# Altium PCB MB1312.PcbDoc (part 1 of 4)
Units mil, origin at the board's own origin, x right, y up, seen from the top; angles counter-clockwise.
Board outline 2755.91 x 5249.6 mil, 6 copper layers (Top Layer, GND, Signal, PWR, GND (Mid2), Bottom Layer), stack 74.545 mil thick; 297 components, 280 nets, 1142 pads, 623 vias.
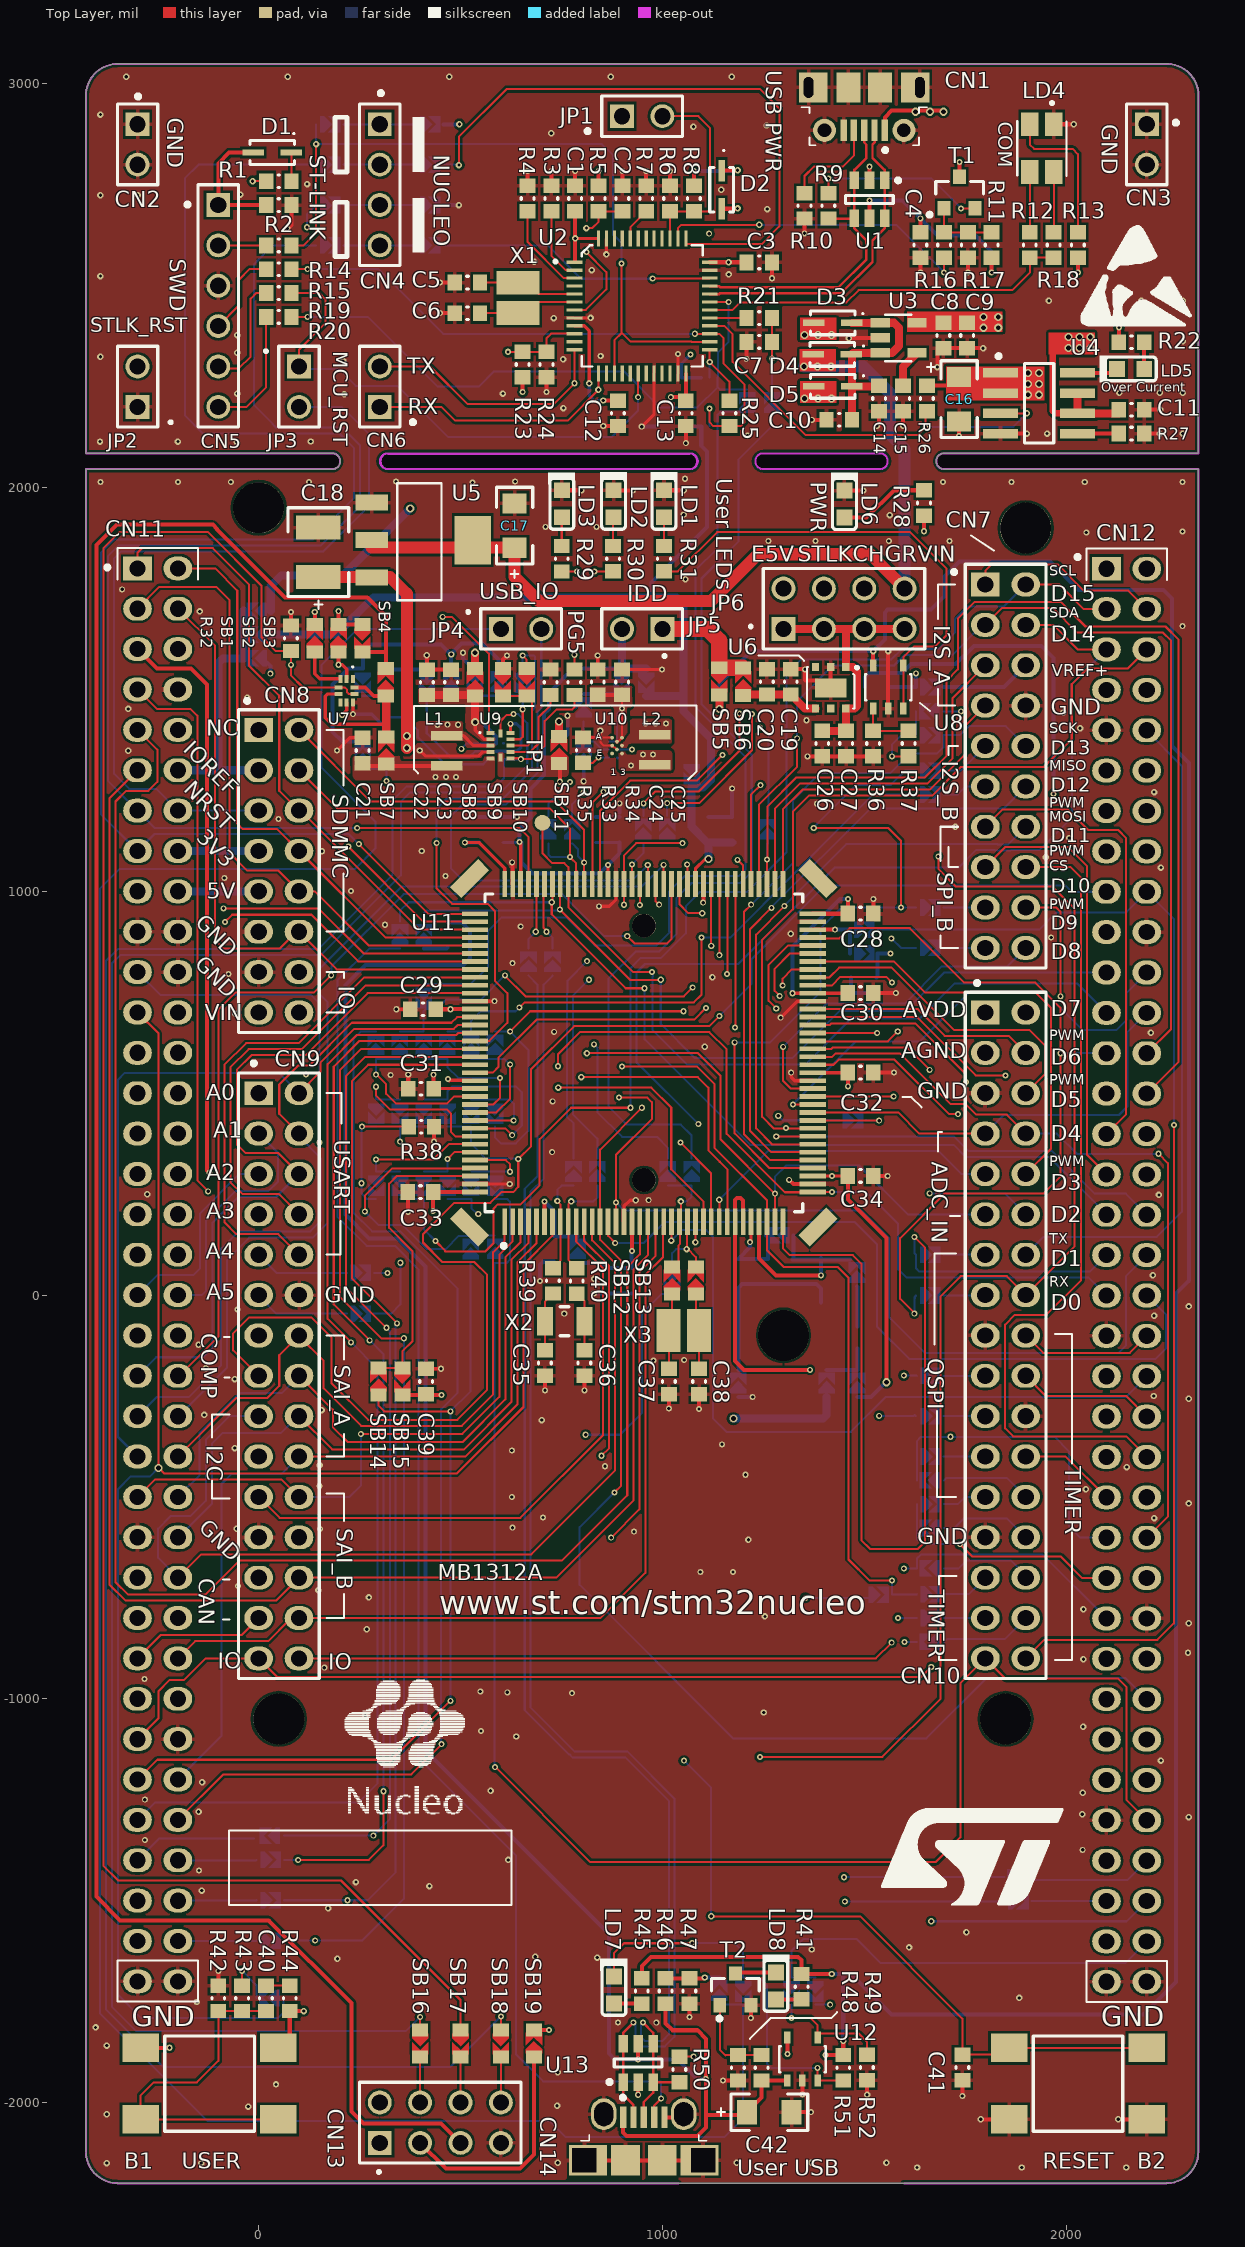
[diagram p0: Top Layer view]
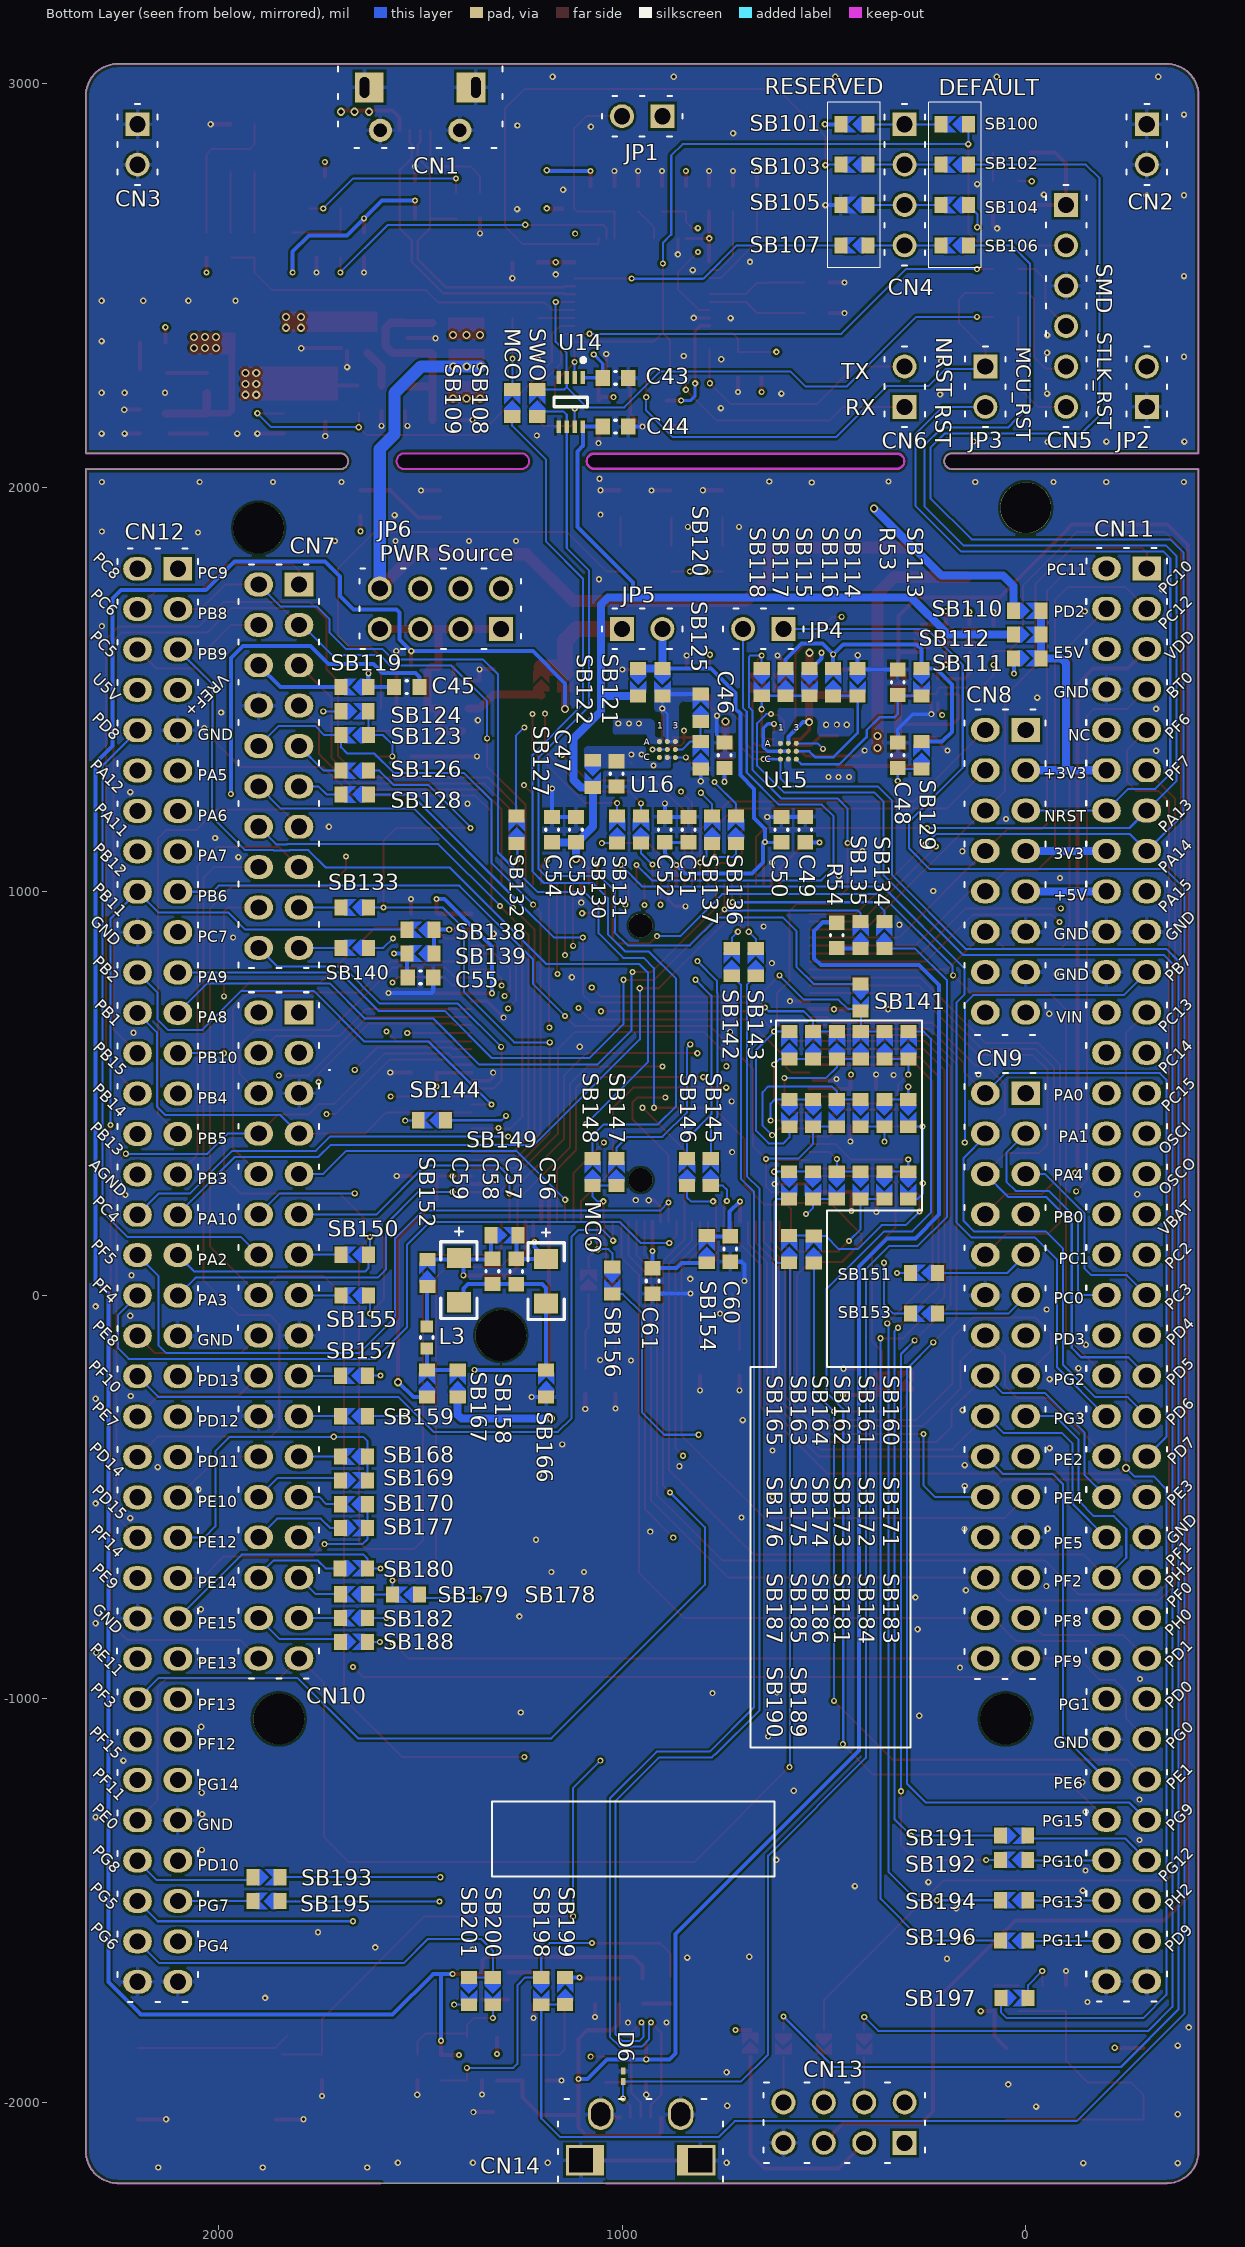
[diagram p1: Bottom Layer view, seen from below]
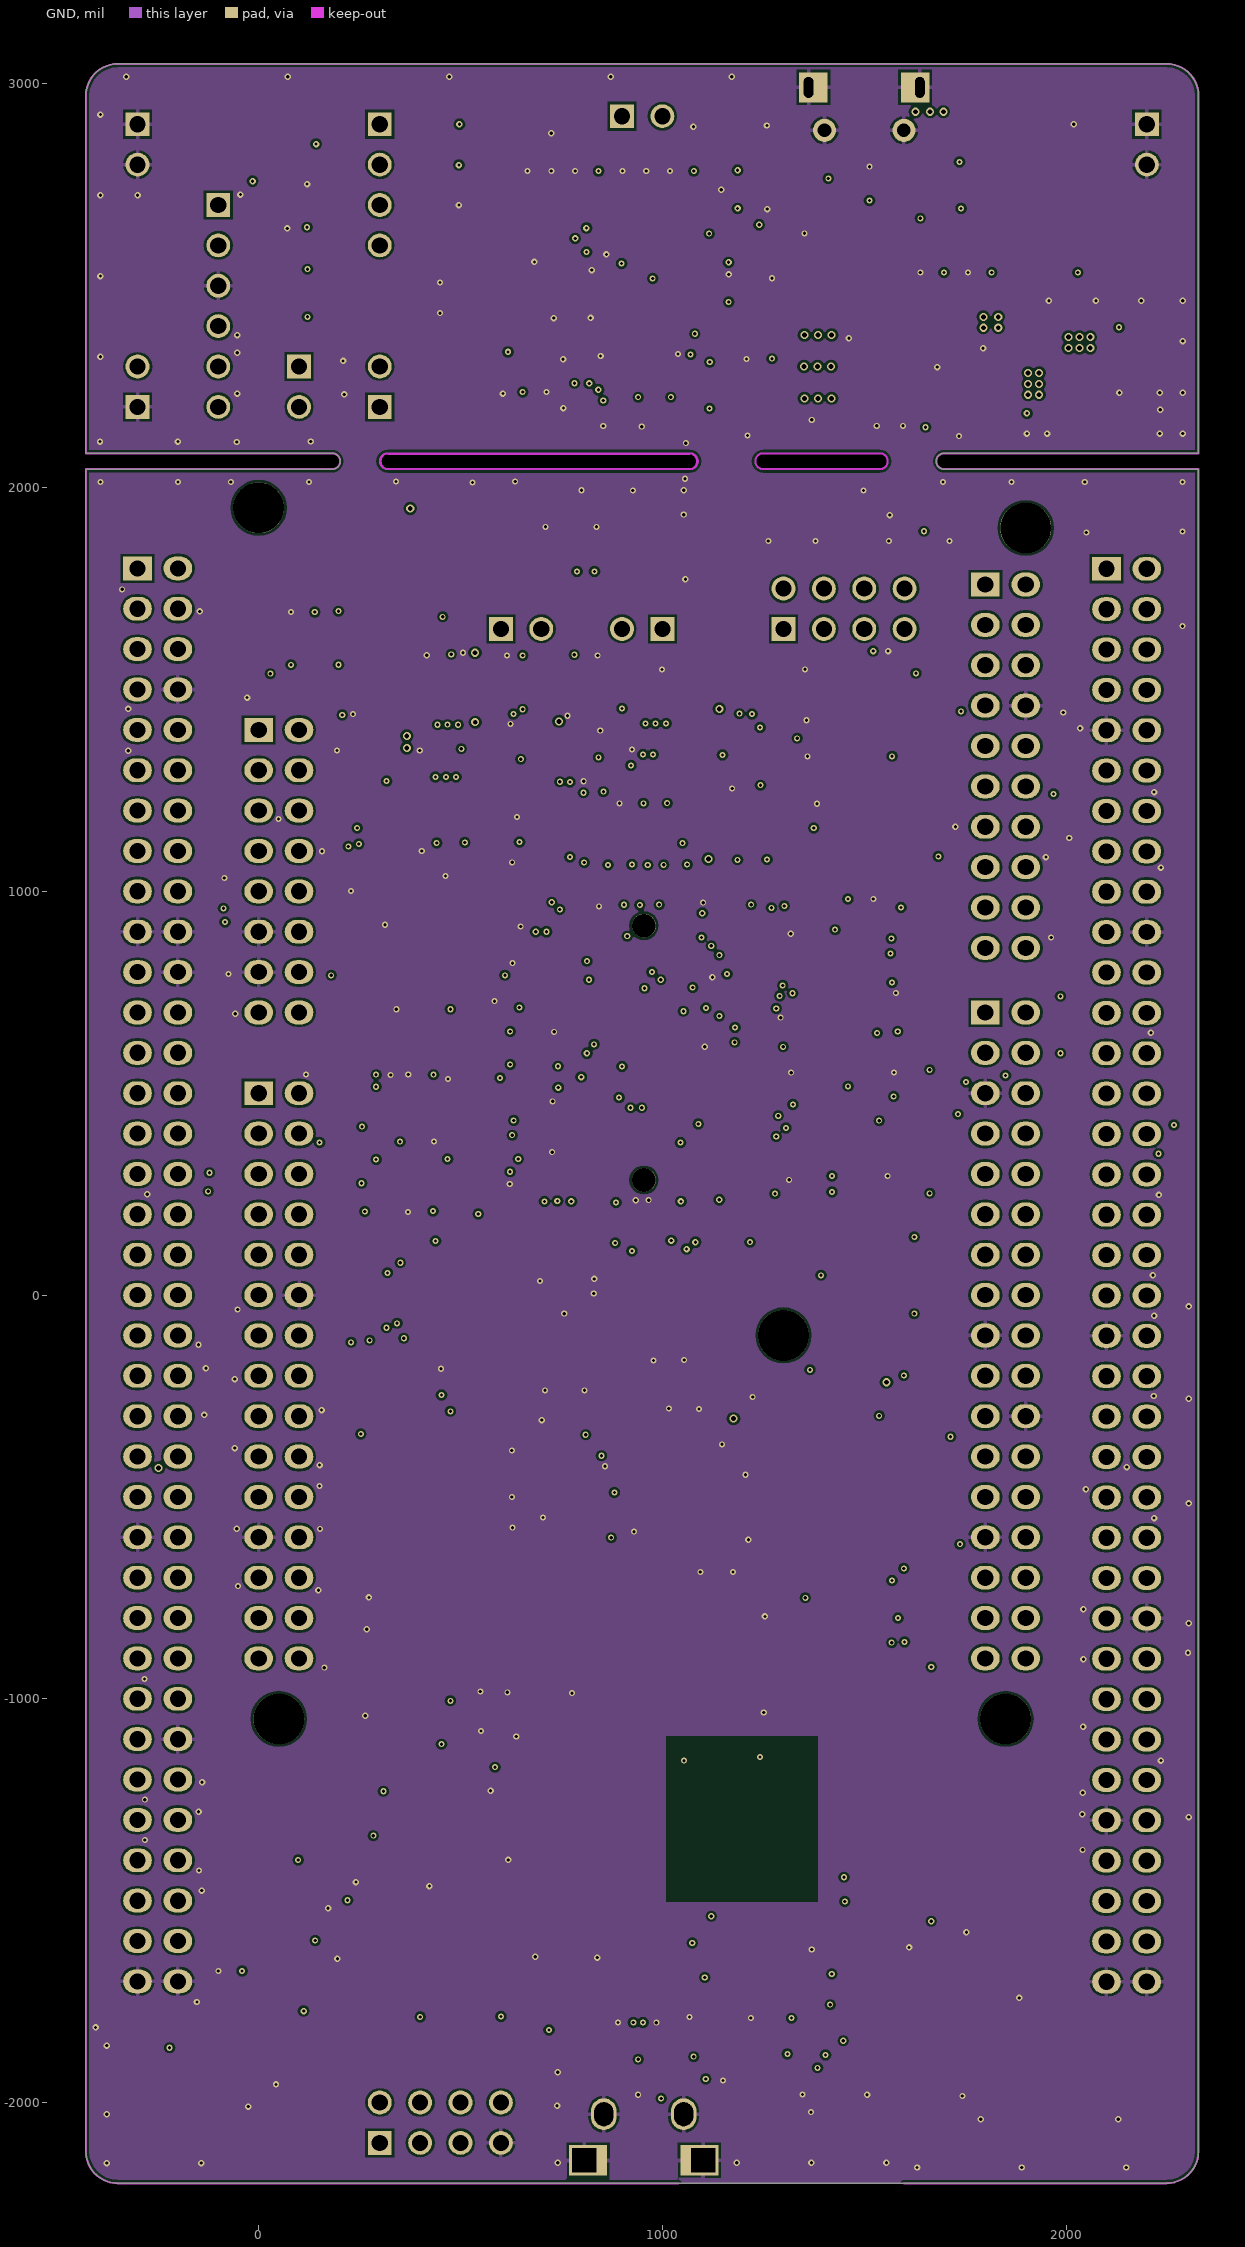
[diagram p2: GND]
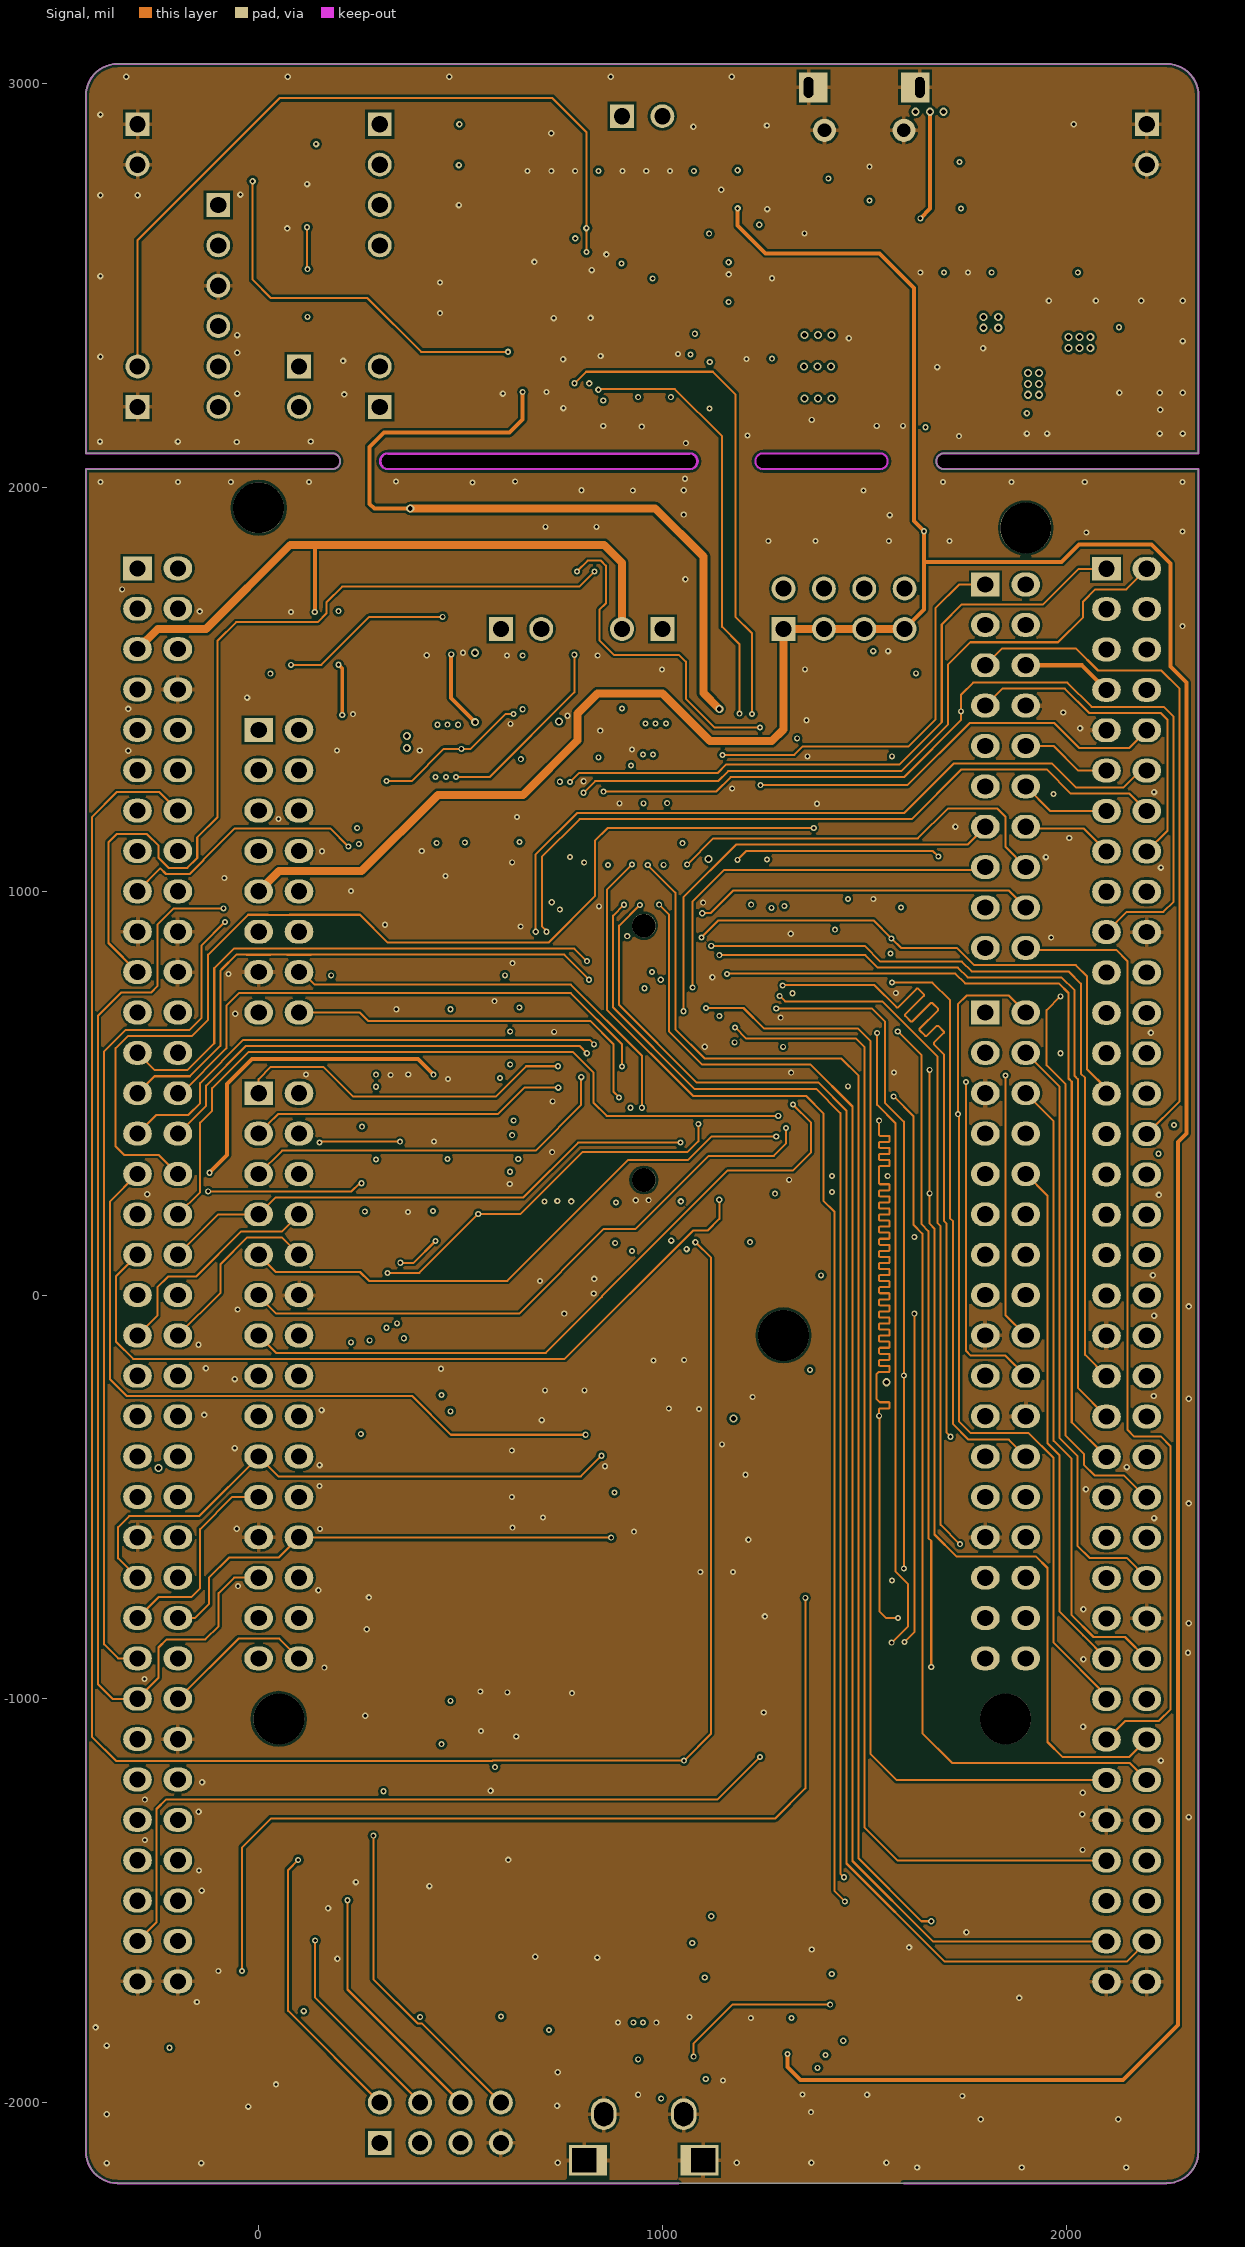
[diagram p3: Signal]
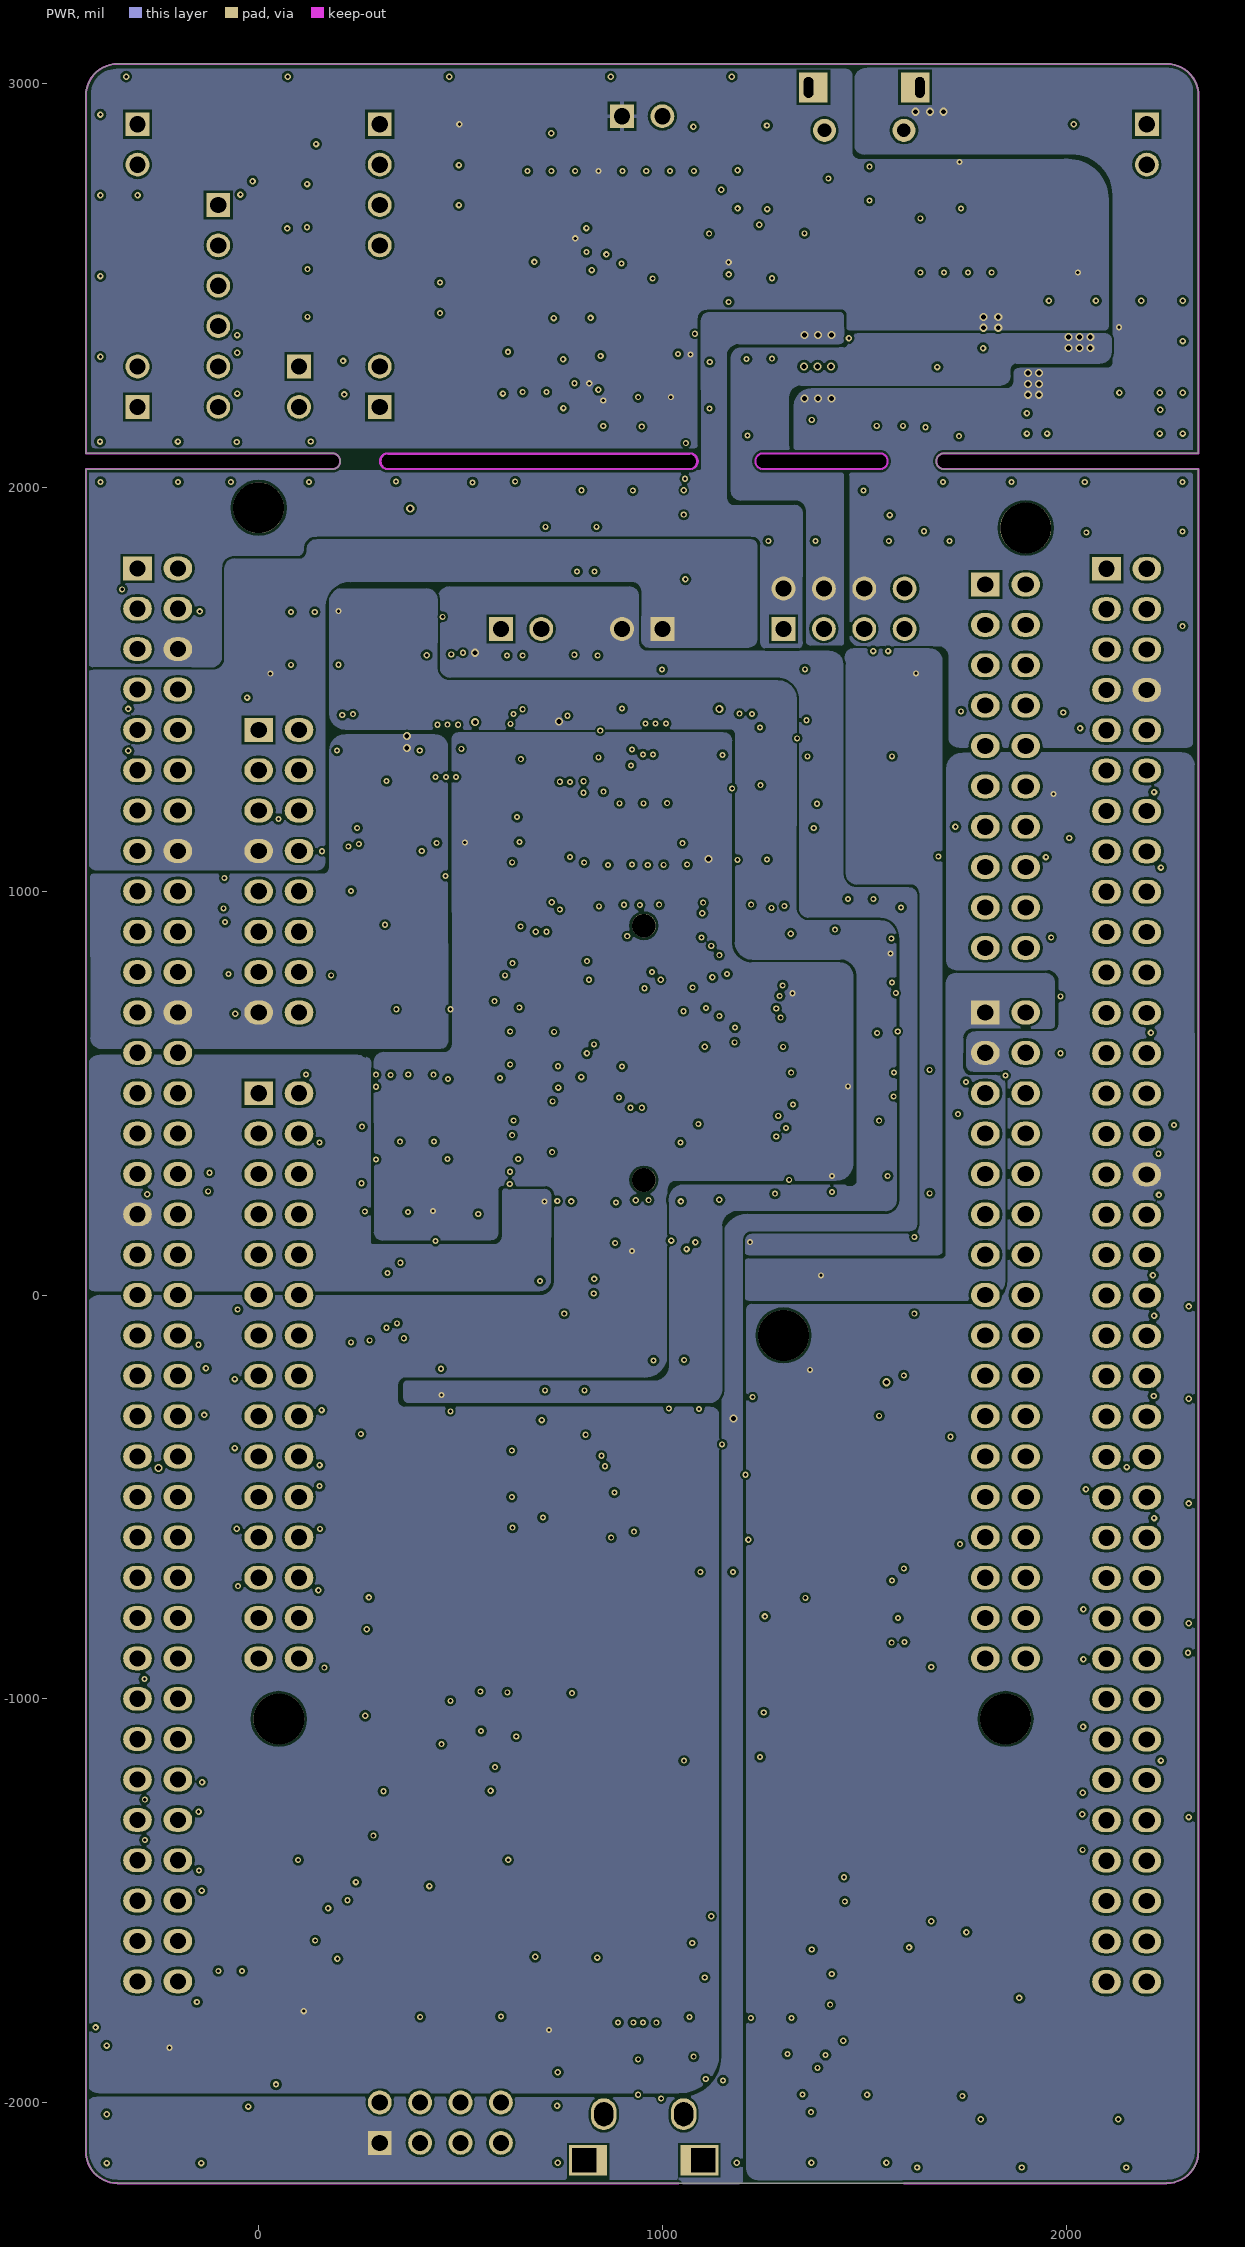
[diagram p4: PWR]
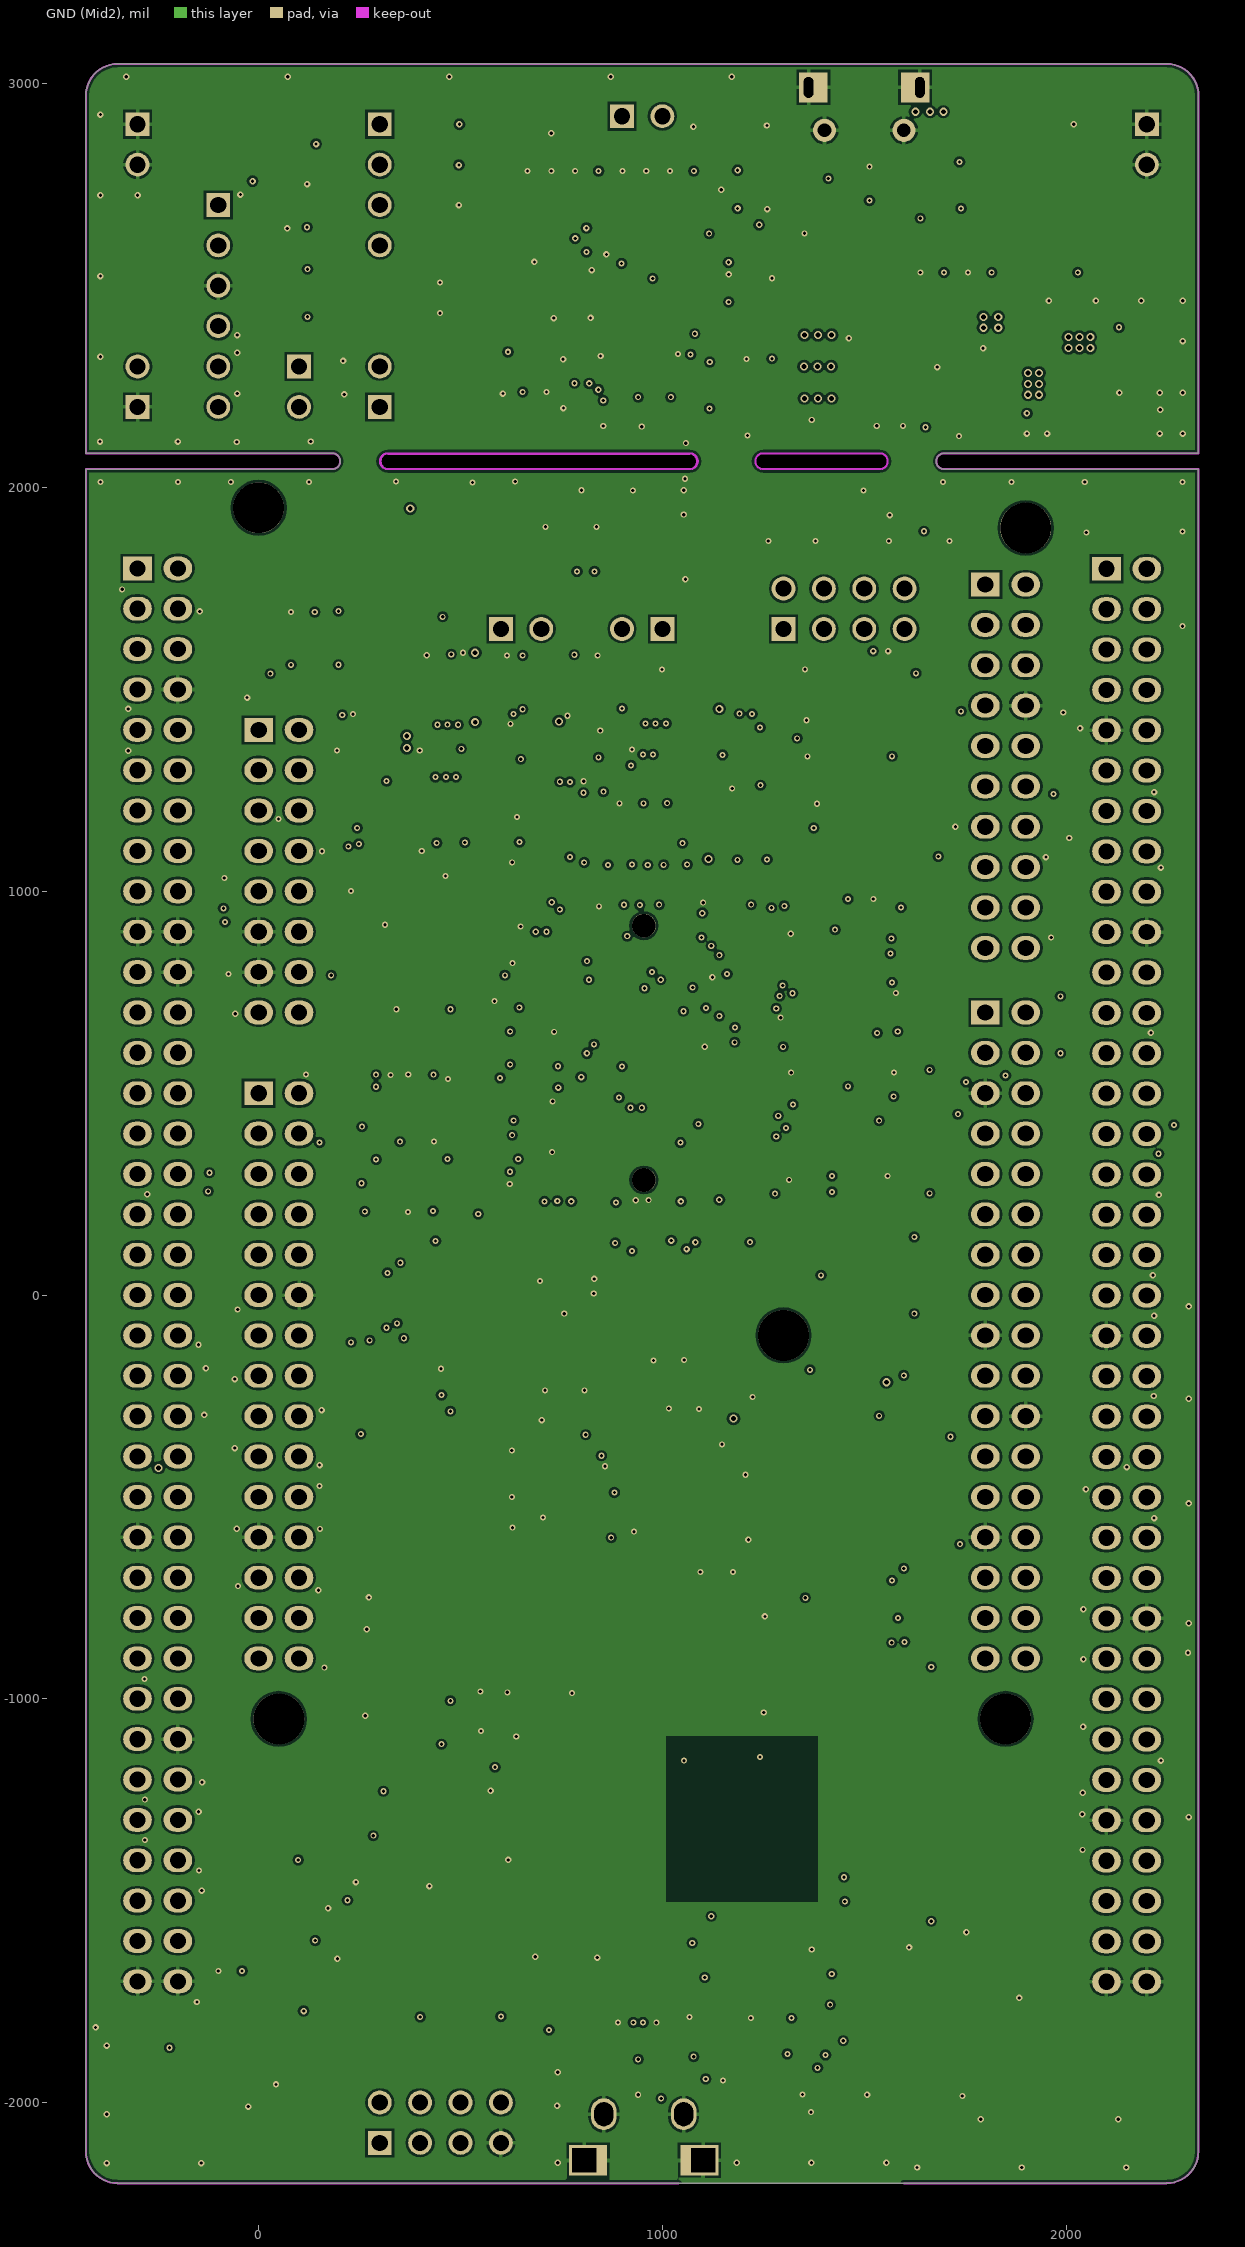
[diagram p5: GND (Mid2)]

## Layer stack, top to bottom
Top Layer: signal copper 1.4
Dielectric: core 15.748, FR-4, Dk 4.8
GND: signal copper 1.4
Dielectric: prepreg 9.4488, FR-4, Dk 4.8
Signal: signal copper 1.4
Dielectric: core 12.6, FR-4, Dk 4.8
PWR: signal copper 1.4
Dielectric: prepreg 12.6, FR-4, Dk 4.8
GND (Mid2): signal copper 1.4
Dielectric: core 15.748, FR-4, Dk 4.8
Bottom Layer: signal copper 1.4

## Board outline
-427.8,-2121.22 ccw(c-349.06,-2121.22) -349.06,-2199.96 -349.21,-2200 2249.21,-2200 2249.22,-2199.8 ccw(c2249.22,-2121.06) 2327.96,-2121.06 2327.96,2045.66 1698.03,2045.66 cw(c1698.03,2065.35) 1698.03,2085.03 2327.96,2085.03 2327.96,2970.86 ccw(c2249.22,2970.86) 2249.22,3049.6 -349.21,3049.6 ccw(c-349.21,2970.86) -427.95,2970.86 -427.95,2085.03 182.29,2085.03 cw(c182.29,2065.35) 182.29,2045.66 -427.95,2045.66
cut-out: 1250,2045.67 cw(c1250,2065.35) 1250,2085.04 1538.58,2085.04 cw(c1538.58,2065.35) 1538.58,2045.67
cut-out: 320.08,2048.18 320.1,2048.18 569.42,2048.18 1068.11,2048.18 cw(c1068.11,2045.67) 1068.13,2048.18 ccw(c1068.11,2065.35) 1085.28,2065.35 ccw(c1068.11,2065.35) 1068.11,2082.52 cw(c1068.11,2085.04) 1068.08,2082.52 1068.11,2082.52 569.42,2082.52 1068.08,2082.52 569.42,2082.52 320.08,2082.52 ccw(c320.08,2085.04) 320.1,2082.52 320.08,2082.52 569.42,2082.52 320.08,2082.52 ccw(c320.08,2065.35)

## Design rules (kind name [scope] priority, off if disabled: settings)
Clearance U7_PAD [(ObjectKind = 'Pad') And (Component = 'U7') vs (ObjectKind = 'Pad') And (Component = 'U7')] p1: gap=5.9
Clearance U9_PAD [(ObjectKind = 'Pad') And (Component = 'U9') vs (ObjectKind = 'Pad') And (Component = 'U9')] p2: gap=5.9
Clearance SB [(HasFootprint('SB_0603')) or (HasFootprint('JP2_SMD'))] p3: gap=5
Clearance D6_PAD [(ObjectKind = 'Pad') And (Component = 'D300') vs (ObjectKind = 'Pad') And (Component = 'D300')] p4: gap=7.8
Clearance Polygon [(ObjectKind = 'Poly')] p5: gap=10
Clearance [All] p6: gap=6
DiffPairsRouting [All] p1: maxlimit=10 minlimit=8.9 mostfreqgap=8.9 maxuncoupledlength=500
FabricationTestPointUsage TestPointUsage [All] p1: valid=0 allowmultiple=FALSE
FabricationTestpoint Testpoint [(IsPad And (OnTopLayer Or OnBottomLayer))] p1: side=3 testpointundercomponent=TRUE minsize=40 maxsize=100 preferedsize=60 minholesize=0 maxholesize=40 preferedholesize=32 testpointgrid=1 allowsidetop=TRUE allowsidebottom=TRUE usegrid=TRUE gridtolerance=0.01
HoleSize [All] p1: absolutevalues=TRUE maxlimit=150 minlimit=1 maxpercent=80.000 minpercent=20.000
MinimumSolderMaskSliver [All] p1: minsoldermaskwidth=0
PolygonConnect netc315 [(ObjectKind = 'Poly') And (Net = 'NetC315_2')] p1: connectstyle=Direct reliefconductorwidth=10 reliefentries=4 polygonreliefangle="90 Angle"
PolygonConnect AVDD [(ObjectKind = 'Poly') And (Net = 'AVDD')] p2: connectstyle=Direct reliefconductorwidth=10 reliefentries=4 polygonreliefangle="90 Angle"
PolygonConnect AGND [(ObjectKind = 'Poly') And (Net = 'AGND')] p3: connectstyle=Direct reliefconductorwidth=10 reliefentries=4 polygonreliefangle="90 Angle"
PolygonConnect netc11 [(ObjectKind = 'Poly') And (Net = 'NetC11_2')] p4: connectstyle=Direct reliefconductorwidth=10 reliefentries=4 polygonreliefangle="90 Angle"
PolygonConnect NETSB368 [(ObjectKind = 'Poly') And (Net = 'NetSB368_1')] p5: connectstyle=Direct reliefconductorwidth=10 reliefentries=4 polygonreliefangle="90 Angle"
PolygonConnect Netc306 [(ObjectKind = 'Poly') And (Net = 'NetC306_2')] p6: connectstyle=Direct reliefconductorwidth=10 reliefentries=4 polygonreliefangle="90 Angle"
PolygonConnect NetL301 [(ObjectKind = 'Poly') And (Net = 'NetL301_1')] p7: connectstyle=Direct reliefconductorwidth=10 reliefentries=4 polygonreliefangle="90 Angle"
PolygonConnect Net308 [(ObjectKind = 'Poly') And (Net = 'NetC308_2')] p8: connectstyle=Direct reliefconductorwidth=10 reliefentries=4 polygonreliefangle="90 Angle"
PolygonConnect netc303 [(ObjectKind = 'Poly') And (Net = 'NetC303_2')] p9: connectstyle=Direct reliefconductorwidth=10 reliefentries=4 polygonreliefangle="90 Angle"
PolygonConnect netl300 [(ObjectKind = 'Poly') And (Net = 'NetL300_1')] p10: connectstyle=Direct reliefconductorwidth=10 reliefentries=4 polygonreliefangle="90 Angle"
PolygonConnect NETC304 [(ObjectKind = 'Poly') And (Net = 'NetC304_2')] p11: connectstyle=Direct reliefconductorwidth=10 reliefentries=4 polygonreliefangle="90 Angle"
PolygonConnect VBAT [(ObjectKind = 'Poly') And (Net = 'VBAT')] p12: connectstyle=Direct reliefconductorwidth=10 reliefentries=4 polygonreliefangle="90 Angle"
PolygonConnect VDD [(ObjectKind = 'Poly') And (Net = 'VDD')] p13: connectstyle=Direct reliefconductorwidth=10 reliefentries=4 polygonreliefangle="90 Angle"
PolygonConnect VIN [(ObjectKind = 'Poly') And (Net = 'VIN')] p14: connectstyle=Direct reliefconductorwidth=10 reliefentries=4 polygonreliefangle="90 Angle"
PolygonConnect +3V3 [(ObjectKind = 'Poly') And (Net = '+3V3')] p15: connectstyle=Direct reliefconductorwidth=10 reliefentries=4 polygonreliefangle="90 Angle"
PolygonConnect E5V [(ObjectKind = 'Poly') And (Net = 'E5V')] p16: connectstyle=Direct reliefconductorwidth=10 reliefentries=4 polygonreliefangle="90 Angle"
PolygonConnect +5V [(ObjectKind = 'Poly') And (Net = '+5V')] p17: connectstyle=Direct reliefconductorwidth=10 reliefentries=4 polygonreliefangle="90 Angle"
PolygonConnect U5V [(ObjectKind = 'Poly') And (Net = 'U5V')] p18: connectstyle=Direct reliefconductorwidth=10 reliefentries=4 polygonreliefangle="90 Angle"
PolygonConnect VIA [IsVia] p19: connectstyle=Direct reliefconductorwidth=20 reliefentries=4 polygonreliefangle="90 Angle"
PolygonConnect [All] p20: connectstyle=Relief reliefconductorwidth=10 reliefentries=4 polygonreliefangle="90 Angle"
RoutingLayers [All] p1: top layer_v5=FALSE mid layer 1_v5=FALSE mid layer 2_v5=FALSE mid layer 3_v5=FALSE mid layer 4_v5=FALSE bottom layer_v5=FALSE
RoutingVias [All] p1: holewidth=12 width=20 viastyle="Through Hole" minholewidth=8 minwidth=15 maxholewidth=28 maxwidth=50
SilkToSilkClearance [All] p1: silktosilkclearance=4
SilkscreenOverComponentPads [IsPad] p1: minsilkscreentomaskgap=4
SolderMaskExpansion [All] p1: expansion=4
Width PWR [InNetClass('PWR')] p1: maxlimit=100 minlimit=8 preferedwidth=10 midlayer1_minwidth=10 midlayer2_minwidth=10 midlayer3_minwidth=10 midlayer4_minwidth=10 bottomlayer_minwidth=10 minimp=50.000000 maximp=50.000000 favimp=50.000000
Width [All] p2: maxlimit=100 minlimit=5 preferedwidth=5 minimp=50.000000 maximp=50.000000 favimp=50.000000
20 further rules are at their usual default settings.

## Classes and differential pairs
net class PH[0..1]: PH0 PH1
component class "U_SMPS power supply": C21 C22 C23 C24 C25 C46 C47 C48 CN13 L1 L2 R32 R33 R34 R35 R53 SB1 SB2 SB3 SB4 SB7 SB8 SB9 SB10 SB11 SB16 SB17 SB18 SB19 SB113 SB114 SB115 SB116 SB117 SB118 SB120 SB121 SB122 SB125 SB127 SB129 U7 U9 U10 U15 U16
component class U_Connectors: C45 CN7 CN8 CN9 CN10 CN11 CN12 LD1 R31 R36 R37 SB110 SB111 SB112 SB119 SB123 SB124 SB126 SB128 SB133 SB136 SB137 SB140 SB144 SB145 SB146 SB147 SB150 SB151 SB153 SB155 SB156 SB157 SB159 SB168 SB169 SB170 SB177 SB179 SB180 SB182 SB188 SB191 SB192 SB193 SB194 SB195 SB196 SB300 SB301 SB374 U8
component class U_ST_LINK_V2-1: C1 C2 C3 C4 C5 C6 C7 C8 C9 C10 C12 C13 C14 C15 C43 C44 CN1 CN2 CN3 CN4 CN5 CN6 D1 D2 D3 D4 D5 JP1 JP2 JP3 LD4 R1 R2 R3 R4 R5 R6 R7 R8 R9 R10 R11 R12 R13 R14 R15 R16 R17 R18 R19 R20 R21 R23 R24 R25 SB100 SB101 SB102 SB103 SB104 SB105 SB106 SB107 SB108 SB109 SB141 SB321 T1 U1 U2 U3 U14 X1
net class PC[0..15]: PC0 PC1 PC2 PC3 PC4 PC5 PC6 PC7 PC8 PC9 PC10 PC11 PC12 PC13 PC14 PC15
net class PB[0..15]: PB0 PB1 PB2 PB3 PB4 PB5 PB6 PB7 PB8 PB9 PB10 PB11 PB12 PB13 PB14 PB15
net class PA[0..15]: PA0 PA1 PA2 PA3 PA4 PA5 PA6 PA7 PA8 PA9 PA10 PA11 PA12 PA13 PA14 PA15
net class PD[0..15]: PD0 PD1 PD2 PD3 PD4 PD5 PD6 PD7 PD8 PD9 PD10 PD11 PD12 PD13 PD14 PD15
net class PE[0..15]: PE0 PE1 PE2 PE3 PE4 PE5 PE6 PE7 PE8 PE9 PE10 PE11 PE12 PE13 PE14 PE15
net class PF[0..15]: PF0 PF1 PF2 PF3 PF4 PF5 PF6 PF7 PF8 PF9 PF10 PF11 PF12 PF13 PF14 PF15
net class PG[0..15]: PG0 PG1 PG2 PG3 PG4 PG5 PG6 PG7 PG8 PG9 PG10 PG11 PG12 PG13 PG14 PG15
component class MB1312: C11 C16 C17 C18 C19 C20 C26 C27 JP5 JP6 LD5 LD6 R22 R26 R27 R28 SB5 SB6 U4 U5 U6
component class U_STM32L_144: B1 B2 C28 C29 C30 C31 C32 C33 C34 C35 C36 C37 C38 C39 C40 C41 C49 C50 C51 C52 C53 C54 C55 C56 C57 C58 C59 C60 C61 C310 C313 JP4 L3 LD2 LD3 R29 R30 R38 R39 R40 R42 R43 R44 R54 SB12 SB13 SB14 SB15 SB130 SB131 SB132 SB134 SB135 SB138 SB139 SB142 SB143 SB148 SB149 SB152 SB154 SB158 SB160 SB161 SB162 SB163 SB164 SB165 SB166 SB167 SB171 SB172 SB173 SB174 SB175 SB176 SB178 SB181 SB183 SB184 SB185 SB186 SB187 SB189 SB190 SB197 SB341 SB349 TP1 U11 X2 X3
component class U_USB: C42 CN14 CN300 D6 D300 LD7 LD8 R41 R45 R46 R47 R48 R49 R50 R51 R52 R61 R62 R63 R64 R68 R69 R70 R71 R72 R76 SB198 SB199 SB200 SB201 SB352 SB354 T2 U12 U13 U306

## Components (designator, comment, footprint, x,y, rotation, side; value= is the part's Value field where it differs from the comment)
B1 "USER (Blue)" PB-6X6mm-Blue -122,-1953 r180 top
B2 "TD-0341 [RESET/Black]" PB-6X6mm-Black 2029,-1953 r180 top
C1 "100nF" 0603C 784,2716 r270 top
C2 "100nF" 0603C 901,2716 r270 top
C3 "100nF" 0603C 1240,2558 r180 top
C4 "100nF" 0603C 1639,2601 r90 top
C5 "10pF" 0603C 517,2508 r180 top
C6 "10pF" 0603C 517,2432 r180 top
C7 "20pF[N/A]" 0603C 1240,2361 r180 top
C8 "100nF" 0603C 1696,2377 r90 top locked
C9 "1uF_X5R_0603" 0603C 1755,2377 r270 top
C10 "100nF" 0603C 1438,2168 r0 top
C11 "100nF" 0603C 2162,2193 r180 top
C12 "100nF" 0603C 890,2184 r90 top
C13 "100nF" 0603C 1058,2184 r90 top
C14 "1uF_X5R_0603" 0603C 1537,2221 r90 top
C15 "10nF_X7R_0603" 0603C 1596,2221 r90 top
C16 "4.7uF" TAN-A 1735,2219 r90 top
C17 "10uF" TAN-A 634,1906 r270 top (schematic designator C18)
C18 "10uF(25V)" TAN-B 148,1840 r270 top (schematic designator C17)
C19 "1uF_X5R_0603" 0603C 1318,1519 r90 top (schematic designator C20)
C20 "100nF" 0603C 1259,1519 r270 top (schematic designator C19)
C21 "10uF" 0603C 257.53,1348.75 r270 top (schematic designator C308)
C22 "10uF" 0603C 416.59,1517.75 r270 top (schematic designator C306)
C23 "100nF" 0603C 476.84,1517.75 r90 top (schematic designator C307)
C24 "100nF" 0603C 839.83,1518.25 r90 top (schematic designator C305)
C25 "10uF" 0603C 900.31,1518.25 r270 top (schematic designator C304)
C26 "100nF" 0603C 1396,1366 r90 top (schematic designator C22)
C27 "1uF_X5R_0603" 0603C 1455,1366 r270 top (schematic designator C23)
C28 "100nF" 0603C 1491,945 r0 top (schematic designator C58)
C29 "100nF" 0603C 407,708 r180 top (schematic designator C28)
C30 "100nF" 0603C 1491,748 r0 top (schematic designator C29)
C31 "100nF" 0603C 402,511 r180 top (schematic designator C33)
C32 "100nF" 0603C 1491,551 r0 top (schematic designator C31)
C33 "100nF" 0603C 401,255 r180 top (schematic designator C39)
C34 "100nF" 0603C 1491,295 r0 top (schematic designator C32)
C35 "2.7pF" 0603C 709,-168 r270 top
C36 "2.7pF" 0603C 807,-168 r270 top
C37 "4.3pF[N/A]" 0603C 1016,-214 r270 top
C38 "4.3pF[N/A]" 0603C 1091,-214 r270 top
C39 "1nF" 0603C 415,-214 r270 top (schematic designator C310)
C40 "[N/A]" 0603C 18,-1742 r270 top (schematic designator C52)
C41 "100nF" 0603C 1743,-1913 r90 top (schematic designator C53)
C42 "4.7uF" TAN-A 1265,-2024 r180 top (schematic designator C54)
C43 "CC0603KRX7R7BB104" 0603C 1016,2272 r0 bottom (schematic designator C301)
C44 "CC0603KRX7R7BB104" 0603C 1016,2151 r180 bottom (schematic designator C302)
C45 "[N/A]" 0603C 1533.25,1506 r180 bottom (schematic designator C300)
C46 "10uF[N/A]" 0603C 746,1337 r270 bottom (schematic designator C315)
C47 "10uF" 0603C 1013.47,1291.06 r90 bottom (schematic designator C303)
C48 "100nF" 0603C 317,1337 r90 bottom (schematic designator C314)
C49 "100nF" 0603C 546,1152.75 r90 bottom (schematic designator C30)
C50 "100nF" 0603C 605,1152.75 r90 bottom (schematic designator C24)
C51 "100nF" 0603C 835,1152.75 r90 bottom (schematic designator C27)
C52 "4.7uF_X5R_0603" 0603C 894,1152.75 r90 bottom (schematic designator C316)
C53 "100nF" 0603C 1114,1152.75 r90 bottom (schematic designator C26)
C54 "4.7uF_X5R_0603" 0603C 1173,1152.75 r90 bottom (schematic designator C21)
C55 "1nF" 0603C 1499,787 r0 bottom (schematic designator C309)
C56 "TAJA105K016R" TAN-A 1188,34.5 r90 bottom (schematic designator C312)
C57 "100nF" 0603C 1262,58.5 r270 bottom (schematic designator C313)
C58 "100nF" 0603C 1321,58.8 r270 bottom (schematic designator C34)
C59 "TAJA105K016R" TAN-A 1404,37 r90 bottom (schematic designator C311)
C60 "1uF_X5R_0603" 0603C 732,114 r270 bottom (schematic designator C57)
C61 "100nF" 0603C 924,35 r270 bottom (schematic designator C25)
CN1 "1050170001" Molex_1050170001 1500,2885 r180 top
CN2 "" HDR_1x2_2R54_V_M -300,2900 r270 top locked
CN3 "" HDR_1x2_2R54_V_M 2200,2900 r270 top locked
CN4 "Header 4" HDR_1x4_2R54_V_M 300,2900 r270 top locked
CN5 "Header 6X1" HDR_1x6_2R54_V_M -100,2700 r270 top locked (schematic designator CN6)
CN6 "" HDR_1x2_2R54_V_M_S 300,2200 r90 top locked (schematic designator CN5)
CN7 "Header 10X2_Female" HDR_10x2_2R54_V_F 1800,1760 r270 top locked
CN8 "Header 8X2_Female" HDR_8x2_2R54_V_F 0,1400 r270 top locked
CN9 "Header 15X2_Female" HDR_15x2_2R54_V_F 0,500 r270 top locked
CN10 "Header 17X2_Female" HDR_17x2_2R54_V_F 1800,700 r270 top locked
CN11 "Header 36X2" HDR_2x36_2R54_V_M -300,1800 r270 top locked
CN12 "Header 36X2" HDR_2x36_2R54_V_M 2100,1799 r270 top locked
CN13 "Header 4X2[N/A]" HDR_4x2_2R54_V_M 300,-2100 r0 top (schematic designator CN300)
CN14 "Micro-AB or Micro-B" "Micro-AB or MicroB" 954,-2086 r0 top
D1 "BAT60JFILM" SOD-323 34,2830 r0 top
D2 "BAT60JFILM" SOD-323 1147,2738 r90 top
D3 "BAT60JFILM" SOD-323 1422,2408 r0 top
D4 "BAT60JFILM" SOD-323 1421,2330 r0 top
D5 "BAT60JFILM" SOD-323 1422,2251 r0 top
D6 "ESDALC6V1-1U2" ESDALC6V1-1U2 997,-1935 r90 bottom (schematic designator D300)
JP1 "" HDR_1x2_2R54_V_M_S 900,2920 r0 top locked
JP2 "" HDR_1x2_2R54_V_M_S -300,2200 r90 top (schematic designator JP301)
JP3 "" HDR_1x2_2R54_V_M_S 100,2300 r270 top (schematic designator JP300)
JP4 "" HDR_1x2_2R54_V_M_S 600,1650 r0 top locked
JP5 "" HDR_1x2_2R54_V_M_S 1000,1650 r180 top
JP6 "Header 4X2" HDR_4x2_2R54_V_M 1300,1650 r0 top locked (schematic designator JP3)
L1 "2.2uH[VLS252010HBX-2R2M-1]" L1008_L0805_CPT 466,1348 r270 top (schematic designator L301)
L2 "2.2uH[VLS252010HBX-2R2M-1]" L1008_L0805_CPT 981,1351 r270 top (schematic designator L300)
L3 "BEAD" 0603L 1483.53,-105 r270 bottom (schematic designator L1)
LD1 "Green" 0603D-G 1004,1960 r270 top
LD2 "Blue" 0603D-B 879,1960 r270 top
LD3 "Red" 0603D-R 751,1960 r270 top
LD4 "LD_BICOLOR_CMS" HSMF-A201 1940,2841 r270 top
LD5 "Red" 0603D-R 2160,2294 r0 top
LD6 "Green" 0603D-G 1451.04,1959.33 r270 top
LD7 "Red" 0603D-R 880,-1721 r270 top
LD8 "Green" 0603D-G 1281.01,-1711 r270 top
R1 "100[N/A]" 0603R 50,2759 r180 top
R2 "10K" 0603R 50,2700 r0 top
R3 "10K" 0603R 725,2716 r270 top (schematic designator R4)
R4 "10K[N/A]" 0603R 666,2716 r270 top (schematic designator R3)
R5 "100K" 0603R 842,2716 r90 top
R6 "4K7" 0603R 1019,2716 r90 top (schematic designator R7)
R7 "100K" 0603R 960,2716 r270 top (schematic designator R6)
R8 "2K7" 0603R 1078,2716 r270 top locked
R9 "1K5" 0603R 1411,2698 r90 top
R10 "100K" 0603R 1352,2698 r270 top (schematic designator R11)
R11 "10K" 0603R 1815.7,2601 r270 top (schematic designator R12)
R12 "100" 0603R 1910,2601 r90 top (schematic designator R13)
R13 "0" 0603R 2029,2601 r270 top (schematic designator R14)
R14 "22" 0603R 50,2600 r0 top (schematic designator R10)
R15 "22" 0603R 50,2541 r0 top (schematic designator R19)
R16 "100" 0603R 1697.7,2601 r270 top (schematic designator R15)
R17 "36K" 0603R 1756.7,2601 r90 top (schematic designator R16)
R18 "100" 0603R 1969,2601 r90 top (schematic designator R17)
R19 "22" 0603R 50,2482 r0 top (schematic designator R22)
R20 "22" 0603R 50,2423 r0 top (schematic designator R23)
R21 "100" 0603R 1240,2420 r0 top (schematic designator R20)
R22 "1K" 0603R 2162,2360 r0 top (schematic designator R21)
R23 "4K7" 0603R 654,2304.7 r90 top (schematic designator R25)
R24 "4K7" 0603R 713,2304.7 r90 top
R25 "100[N/A]" 0603R 1166,2184 r270 top (schematic designator R26)
R26 "10K" 0603R 1655,2221 r270 top (schematic designator R27)
R27 "2K7" 0603R 2162,2134 r180 top (schematic designator R28)
R28 "1K" 0603R 1648,1962 r270 top (schematic designator R29)
R29 "1K" 0603R 750.75,1823.97 r90 top (schematic designator R30)
R30 "680" 0603R 878,1824 r90 top (schematic designator R31)
R31 "510" 0603R 1004,1824 r90 top (schematic designator R32)
R32 "33K" 0603R 80,1627 r90 top (schematic designator R302)
R33 "0" 0603R 723,1518 r270 top (schematic designator R304)
R34 "1M" 0603R 782,1518 r270 top (schematic designator R301)
R35 "19.6K[1%]" 0603R 803,1349.75 r270 top (schematic designator R300)
R36 "200K" 0603R 1522,1366 r270 top (schematic designator R33)
R37 "10K" 0603R 1610,1366 r270 top (schematic designator R34)
R38 "10K" 0603R 403,417 r0 top (schematic designator R36)
R39 "0" 0603R 729,35.25 r90 top (schematic designator R37)
R40 "0" 0603R 788,35 r90 top (schematic designator R38)
R41 "330" 0603R 1345.01,-1713 r90 top (schematic designator R64)
R42 "220K" 0603R -100,-1742 r90 top (schematic designator R58)
R43 "330" 0603R -41,-1742 r90 top (schematic designator R59)
R44 "100" 0603R 77,-1742 r90 top (schematic designator R60)
R45 "620" 0603R 949,-1724 r90 top (schematic designator R61)
R46 "430K" 0603R 1008,-1724 r90 top (schematic designator R62)
R47 "620K" 0603R 1067,-1724 r270 top (schematic designator R63)
R48 "22K" 0603R 1187,-1914 r90 top (schematic designator R69)
R49 "47K" 0603R 1246,-1914 r90 top (schematic designator R68)
R50 "1K5" 0603R 1042,-1918 r90 top (schematic designator R70)
R51 "47K" 0603R 1448,-1914 r270 top (schematic designator R71)
R52 "10K" 0603R 1506.68,-1913 r90 top (schematic designator R72)
R53 "11.8K[1%]" 0603R 317,1518 r270 bottom (schematic designator R303)
R54 "10K" 0603R 468,891 r270 bottom (schematic designator R35)
SB1 "Circuit Breaker" SB_0603 139,1627 r270 top (schematic designator SB331)
SB2 "Circuit Breaker" SB_0603 197.77,1627.06 r270 top (schematic designator SB337)
SB3 "Circuit Breaker" SB_0603 257,1627 r90 top (schematic designator SB335)
SB4 "Circuit Breaker" SB_0603 315,1517.75 r270 top (schematic designator SB334)
SB5 "Closed" SB_0603 1141,1520 r90 top locked (schematic designator SB2)
SB6 "Closed" SB_0603 1200,1519 r270 top (schematic designator SB3)
SB7 "Circuit Breaker" SB_0603 316,1348.75 r270 top (schematic designator SB339)
SB8 "Circuit Breaker" SB_0603 536,1517.75 r270 top (schematic designator SB330)
SB9 "Circuit Breaker" SB_0603 605,1518 r90 top (schematic designator SB370)
SB10 "Circuit Breaker" SB_0603 664,1518 r90 top (schematic designator SB366)
SB11 "Circuit Breaker" SB_0603 744,1350 r270 top (schematic designator SB368)
SB12 "Open" SB_0603 1024,36 r270 top locked (schematic designator SB8)
SB13 "Open" SB_0603 1083,36 r270 top locked (schematic designator SB9)
SB14 "Circuit Breaker" SB_0603 297,-214 r270 top (schematic designator SB358)
SB15 "Circuit Breaker" SB_0603 356,-214 r90 top (schematic designator SB360)
SB16 "Circuit Breaker" SB_0603 400,-1854 r90 top (schematic designator SB328)
SB17 "Circuit Breaker" SB_0603 500,-1854 r90 top (schematic designator SB332)
SB18 "Circuit Breaker" SB_0603 600,-1854 r90 top (schematic designator SB329)
SB19 "Open" SB_0603 682,-1854 r270 top (schematic designator SB325)
SB100 "Closed" SB_0603 176,2900 r180 bottom (schematic designator SB101)
SB101 "Open" SB_0603 424,2900 r180 bottom (schematic designator SB102)
SB102 "Closed" SB_0603 176,2800 r180 bottom (schematic designator SB103)
SB103 "Open" SB_0603 424,2800 r180 bottom (schematic designator SB104)
SB104 "Closed" SB_0603 176,2700 r180 bottom (schematic designator SB105)
SB105 "Open" SB_0603 424,2700 r180 bottom (schematic designator SB106)
SB106 "Closed" SB_0603 176,2600 r180 bottom (schematic designator SB108)
SB107 "Open" SB_0603 424,2600 r180 bottom (schematic designator SB109)
SB108 "Open" SB_0603 1210,2209.75 r270 bottom (schematic designator SB321)
SB109 "Open" SB_0603 1272,2209.75 r270 bottom (schematic designator SB112)
SB110 "Open" SB_0603 -3.75,1695 r0 bottom (schematic designator SB113)
SB111 "Open" SB_0603 -3.75,1577 r0 bottom (schematic designator SB114)
SB112 "Closed" SB_0603 -3.75,1636 r0 bottom (schematic designator SB300)
SB113 "Open" SB_0603 258,1518 r90 bottom (schematic designator SB338)
SB114 "Closed" SB_0603 416.3,1518 r90 bottom (schematic designator SB336)
SB115 "Circuit Breaker" SB_0603 535.6,1518.33 r90 bottom (schematic designator SB369)
SB116 "Open" SB_0603 477,1518 r270 bottom (schematic designator SB333)
SB117 "Circuit Breaker" SB_0603 594.6,1518.33 r270 bottom (schematic designator SB340)
SB118 "Circuit Breaker" SB_0603 654,1518.25 r90 bottom (schematic designator SB367)
SB119 "Open" SB_0603 1662.25,1506 r180 bottom (schematic designator SB301)
SB120 "Open" SB_0603 805,1454.75 r270 bottom (schematic designator SB326)
SB121 "Open" SB_0603 899.79,1518 r90 bottom (schematic designator SB323)
SB122 "Closed" SB_0603 960,1518 r90 bottom (schematic designator SB322)
SB123 "Open" SB_0603 1662,1387 r180 bottom (schematic designator SB119)
SB124 "Closed" SB_0603 1662.25,1446 r0 bottom (schematic designator SB120)
SB125 "Closed" SB_0603 805,1337 r270 bottom (schematic designator SB327)
SB126 "Closed" SB_0603 1662,1299 r180 bottom (schematic designator SB302)
SB127 "Open" SB_0603 1072.47,1291.06 r90 bottom (schematic designator SB324)
SB128 "Closed" SB_0603 1662,1240 r180 bottom (schematic designator SB303)
SB129 "Open" SB_0603 258,1337 r270 bottom (schematic designator SB373)
SB130 "Closed" SB_0603 1012,1153 r270 bottom (schematic designator SB6)
SB131 "Closed" SB_0603 953,1153 r270 bottom (schematic designator SB5)
SB132 "Closed" SB_0603 1261,1152.75 r270 bottom (schematic designator SB118)
SB133 "Closed" SB_0603 1662,960 r180 bottom (schematic designator SB304)
SB134 "Circuit Breaker" SB_0603 350,892 r270 bottom (schematic designator SB125)
SB135 "Circuit Breaker" SB_0603 409,892 r270 bottom (schematic designator SB127)
SB136 "Closed" SB_0603 717.7,1152.75 r270 bottom (schematic designator SB117)
SB137 "Closed" SB_0603 776.7,1152.75 r270 bottom (schematic designator SB116)
SB138 "Circuit Breaker" SB_0603 1499,905 r180 bottom (schematic designator SB357)
SB139 "Circuit Breaker" SB_0603 1499,846 r180 bottom (schematic designator SB359)
SB140 "Closed" SB_0603 1662,860 r180 bottom (schematic designator SB305)
SB141 "Closed" SB_0603 409,737 r90 bottom (schematic designator SB110)
SB142 "Closed" SB_0603 728,824.75 r270 bottom (schematic designator SB133)
SB143 "Closed" SB_0603 668.57,824.75 r270 bottom (schematic designator SB132)
SB144 "Closed" SB_0603 1471,433 r180 bottom (schematic designator SB374)
SB145 "Open" SB_0603 780,305 r270 bottom (schematic designator SB144)
SB146 "Open" SB_0603 839,305 r270 bottom (schematic designator SB145)
SB147 "Closed" SB_0603 1013.7,305 r270 bottom (schematic designator SB148)
SB148 "Open" SB_0603 1072.7,305 r270 bottom (schematic designator SB149)
SB149 "Closed" SB_0603 1291,148 r0 bottom (schematic designator SB365)
SB150 "Closed" SB_0603 1662,100 r180 bottom (schematic designator SB306)
SB151 "Open" SB_0603 252,55 r180 bottom (schematic designator SB143)
SB152 "Closed" SB_0603 1482,54.75 r270 bottom (schematic designator SB12)
SB153 "Open" SB_0603 252,-46 r180 bottom (schematic designator SB138)
SB154 "Closed" SB_0603 790,113.75 r270 bottom (schematic designator SB156)
SB155 "Closed" SB_0603 1662,-1 r180 bottom (schematic designator SB307)
SB156 "Closed" SB_0603 1024,36 r90 bottom (schematic designator SB163)
SB157 "Closed" SB_0603 1664,-200 r180 bottom (schematic designator SB308)
SB158 "Closed" SB_0603 1407,-219 r270 bottom (schematic designator SB371)
SB159 "Closed" SB_0603 1664,-300 r180 bottom (schematic designator SB309)
SB160 "Circuit Breaker" SB_0603 290.53,618.75 r270 bottom (schematic designator SB361)
SB161 "Circuit Breaker" SB_0603 349.53,618.75 r270 bottom (schematic designator SB362)
SB162 "Circuit Breaker" SB_0603 408.53,618.73 r270 bottom (schematic designator SB341)
SB163 "Circuit Breaker" SB_0603 526.53,619 r270 bottom (schematic designator SB343)
SB164 "Circuit Breaker" SB_0603 467.53,619 r270 bottom (schematic designator SB342)
SB165 "Circuit Breaker" SB_0603 585.53,619 r270 bottom (schematic designator SB344)
SB166 "Closed" SB_0603 1188,-219 r270 bottom (schematic designator SB162)
SB167 "Open" SB_0603 1483,-219 r270 bottom (schematic designator SB372)
SB168 "Closed" SB_0603 1664,-400 r180 bottom (schematic designator SB310)
SB169 "Closed" SB_0603 1664,-459 r0 bottom (schematic designator SB312)
SB170 "Closed" SB_0603 1664,-518 r180 bottom (schematic designator SB311)
SB171 "Circuit Breaker" SB_0603 291,450.75 r90 bottom (schematic designator SB350)
SB172 "Circuit Breaker" SB_0603 350,450.75 r90 bottom (schematic designator SB349)
SB173 "Circuit Breaker" SB_0603 409,450.75 r90 bottom (schematic designator SB348)
SB174 "Circuit Breaker" SB_0603 468,450.75 r90 bottom (schematic designator SB347)
SB175 "Circuit Breaker" SB_0603 526.53,450.75 r90 bottom (schematic designator SB346)
SB176 "Circuit Breaker" SB_0603 585.3,450.75 r90 bottom (schematic designator SB345)
SB177 "Closed" SB_0603 1664,-577 r0 bottom (schematic designator SB315)
SB178 "Open" SB_0603 1535,-742 r180 bottom (schematic designator SB180)
SB179 "Closed" SB_0603 1664,-741 r180 bottom
SB180 "Closed" SB_0603 1664.25,-677 r0 bottom (schematic designator SB317)
SB181 "Circuit Breaker" SB_0603 409,271.75 r90 bottom (schematic designator SB351)
SB182 "Closed" SB_0603 1664,-800 r180 bottom (schematic designator SB319)
SB183 "Circuit Breaker" SB_0603 291,271.75 r90 bottom (schematic designator SB363)
SB184 "Circuit Breaker" SB_0603 350,271.75 r90 bottom (schematic designator SB364)
SB185 "Circuit Breaker" SB_0603 527,271.75 r90 bottom (schematic designator SB353)
SB186 "Circuit Breaker" SB_0603 468,271.75 r90 bottom (schematic designator SB352)
SB187 "Circuit Breaker" SB_0603 586,271.75 r90 bottom (schematic designator SB354)
SB188 "Closed" SB_0603 1664,-859 r0 bottom (schematic designator SB320)
SB189 "Circuit Breaker" SB_0603 525,112.75 r270 bottom (schematic designator SB356)
SB190 "Circuit Breaker" SB_0603 586,113.75 r270 bottom (schematic designator SB355)
SB191 "Closed" SB_0603 28.75,-1339 r0 bottom (schematic designator SB313)
SB192 "Closed" SB_0603 28.75,-1399 r180 bottom (schematic designator SB314)
SB193 "Closed" SB_0603 1880.75,-1442 r0 bottom (schematic designator SB4)
SB194 "Closed" SB_0603 28.75,-1499 r180 bottom (schematic designator SB316)
SB195 "Closed" SB_0603 1880.75,-1501 r180 bottom (schematic designator SB7)
SB196 "Closed" SB_0603 28.75,-1599 r180 bottom (schematic designator SB318)
SB197 "Closed" SB_0603 28,-1741 r0 bottom (schematic designator SB173)
SB198 "Circuit Breaker" SB_0603 1200,-1724 r90 bottom (schematic designator SB185)
SB199 "Circuit Breaker" SB_0603 1141,-1723.94 r270 bottom (schematic designator SB184)
SB200 "Circuit Breaker" SB_0603 1320,-1724 r90 bottom (schematic designator SB187)
SB201 "Circuit Breaker" SB_0603 1379,-1724 r90 bottom (schematic designator SB186)
T1 "9013" SOT-23 1736,2731 r0 top locked
T2 "9013" SOT-23 1181.01,-1720 r0 top
TP1 "USB_SOF" TP 703,1170 r0 top
U1 "USBLC6-2SC6" SOT23-6L 1513,2714 r270 top
U2 "STM32F103CBT6" LQFP48_0R5_7x7 950,2450 r270 top locked
U3 "LDK120M33R" SOT23-5 1585,2371 r0 top locked
U4 "ST890CDR" SOIC8_1R27_4R9X6 1933,2209 r0 top locked
U5 "LDK1117S50TR" SOT-223 405,1870 r0 top
U6 "LD39050PU33R" DFN6_0R95_3x3_TP 1417,1504 r180 top
U7 "STG3684AUTR" QFN40P180X140X55-10N 218,1497 r270 top (schematic designator U304)
U8 "TSV631AILT" SOT-23-5L 1559.5,1506 r90 top (schematic designator U7)
U9 "ST1PS02D1QTR" QFN0P170X200X55-12N 599,1361 r0 top (schematic designator U305)
U10 "ST1PS01EJR" Flipchip8 887.69,1361.1 r0 top (schematic designator U301)
U11 "STM32L_LQFP144" LQFP144_0R5_SKT 954,600 r0 top locked (schematic designator U8)
U12 "STMPS2151STR" SOT-23-5L 1347,-1892 r90 top
U13 "USBLC6-2SC6" SOT23-6L 940,-1902 r90 top (schematic designator U306)
U14 "SN74LVC2T45DCUT" USOP8_0R5_2X3R1 1127,2212 r270 bottom (schematic designator U300)
U15 "ADP5301ACBZ-2-R7" WLCSP-9ball 588,1347 r180 bottom (schematic designator U303)
U16 "ADP5301ACBZ-2-R7" WLCSP-9ball 887.69,1351.26 r180 bottom (schematic designator U302)
X1 "NX3225GD-8.000M-EXS00A-CG04874" OSC_2SM_3R2x2R5 642,2470 r90 top
X2 "NX3215SA-32.768KHZ-EXS00A-MU00525" XTAL_2SM_3R2X1R5 758,-65 r180 top
X3 "NX3225GD-8.000M-EXS00A-CG04874[N/A]" OSC_2SM_3R2x2R5 1053,-88 r180 top

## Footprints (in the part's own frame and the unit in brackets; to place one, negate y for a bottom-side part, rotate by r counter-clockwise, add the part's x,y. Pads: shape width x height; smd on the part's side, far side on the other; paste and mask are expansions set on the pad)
0603C [mm] "Chip Capacitor, Body 1.6x0.8mm, Height 1.0mm, IPC Medium Density"
  rect 0.9x1 smd: 1(-0.8,0) 2(0.8,0)
  silkscreen extent -0.05,-0.4 0.05,0.4, body extent -0.87,-0.48 0.88,0.47, height 1
0603D-B [mm] "LED, SMT, Body 1.6 x 0.8 mm, 0.25mm Thickness"
  rect 1x1 smd paste+0 mask+0: 1(0.85,0) 2(-0.85,0)
  silkscreen extent -1.99,-0.85 1.6,0.85, body extent -0.8,-0.4 0.8,0.4, height 0.25
0603D-G [mm] "LED, SMT, Body 1.6 x 0.8 mm, 0.25mm Thickness"
  rect 1x1 smd paste+0 mask+0: 1(0.85,0) 2(-0.85,0)
  silkscreen extent -1.99,-0.84 1.6,0.86, body extent -0.8,-0.4 0.8,0.4, height 0.25
0603D-R [mm] "LED, SMT, Body 1.6 x 0.8 mm, 0.25mm Thickness"
  rect 1x1 smd paste+0 mask+0: 1(0.85,0) 2(-0.85,0)
  silkscreen extent -1.98,-0.86 1.6,0.84, body extent -0.8,-0.4 0.8,0.4, height 0.25
0603L [mil] "Bead 0603L"
  rect 30x30 smd: 1(27.5,0) 2(-27.5,0)
  silkscreen extent -2,-16 2,16, body extent -34,-19 34,19, height 24
0603R [mm] "Chip Resistor, Body 1.6x0.8mm, IPC Medium Density"
  rect 0.9x1 smd: 1(-0.8,0) 2(0.8,0)
  silkscreen extent -0.05,-0.4 0.05,0.4, body extent -0.85,-0.47 0.85,0.47, height 0.6
DFN6_0R95_3x3_TP [mm] "500 mA low quiescent current and low noise voltage regulator"
  rect 2x1.2 smd: 0(0,0)
  rect 0.45x0.5 smd: 1(-0.95,-1.3) 2(0,-1.3) 3(0.95,-1.3) 4(0.95,1.3) 5(0,1.3) 6(-0.95,1.3)
  silkscreen extent -1.71,-1.33 1.5,1.3, body extent -1.5,-1.5 1.5,1.5, height 1
ESDALC6V1-1U2 [mm]
  rect 0.45x0.3 smd: 1(-0.325,0) 2(0.325,0)
  body extent -0.31,-0.16 0.31,0.16, height 0.3
Flipchip8 [mm]
  round 0.23 smd: A1(-0.312,0.5) A3(0.312,0.5) B2(0,0.25) C1(-0.312,0) C3(0.312,0) D2(0,-0.25) E1(-0.312,-0.5) E3(0.312,-0.5)
  body extent -0.55,-0.7 0.55,0.7, height 0.55
HDR_1x2_2R54_V_M [mm] "Male Header, Pitch 2.54mm, 4x1 Position, Mated Height 6mm, Tail Length 10mm"
  rect 1.5x1.5 hole 1.02: 1(0,0)
  round 1.5 hole 1.02: 2(2.54,0)
  silkscreen extent -1.88,-1.27 3.81,1.27, body extent -1.27,-1.27 3.81,1.27, height 9
HDR_1x2_2R54_V_M_S [mm] "Male Header, Pitch 2.54mm, 4x1 Position, Mated Height 6mm, Tail Length 3mm"
  rect 1.5x1.5 hole 1.02: 1(0,0)
  round 1.5 hole 1.02: 2(2.54,0)
  silkscreen extent -1.27,-2.21 3.81,1.27, body extent -1.27,-1.27 3.81,1.27, height 9
HDR_1x4_2R54_V_M [mm] "Male Header, Pitch 2.54mm, 4x1 Position, Mated Height 6mm, Tail Length 3mm"
  rect 1.5x1.5 hole 1.02: 1(0,0)
  round 1.5 hole 1.02: 2(2.54,0) 3(5.08,0) 4(7.62,0)
  silkscreen extent -2.08,-1.27 8.89,1.27, body extent -1.27,-1.27 8.89,1.27, height 9
HDR_1x6_2R54_V_M [mm] "Male Header, Pitch 2.54mm, 6x1 Position, Mated Height 6mm, Tail Length 3mm"
  rect 1.5x1.5 hole 1.02: 1(0,0)
  round 1.5 hole 1.02: 2(2.54,0) 3(5.08,0) 4(7.62,0) 5(10.16,0) 6(12.7,0)
  silkscreen extent -1.27,-2.06 13.97,1.27, body extent -1.27,-1.27 13.97,1.27, height 9
HDR_2x36_2R54_V_M [mm] "Male Header, Pitch 2.54mm, 36x2 Position, Mated Height 6mm, Tail Length 3mm"
  rect 1.5x1.8 hole 1.02: 1(0,0)
  oval 1.5x1.8 hole 1.02: 2(0,2.54) 3(2.54,0) 4(2.54,2.54) 5(5.08,0) 6(5.08,2.54) 7(7.62,0) 8(7.62,2.54) 9(10.16,0) 10(10.16,2.54) 11(12.7,0) 12(12.7,2.54) 13(15.24,0) 14(15.24,2.54) 15(17.78,0) 16(17.78,2.54) 17(20.32,0) 18(20.32,2.54) 19(22.86,0) 20(22.86,2.54) 21(25.4,0) 22(25.4,2.54) 23(27.94,0) 24(27.94,2.54) 25(30.48,0) 26(30.48,2.54) 27(33.02,0) 28(33.02,2.54) 29(35.56,0) 30(35.56,2.54) 31(38.1,0) 32(38.1,2.54) 33(40.64,0) 34(40.64,2.54) 35(43.18,0) 36(43.18,2.54) 37(45.72,0) 38(45.72,2.54) 39(48.26,0) 40(48.26,2.54) 41(50.8,0) 42(50.8,2.54) 43(53.34,0) 44(53.34,2.54) 45(55.88,0) 46(55.88,2.54) 47(58.42,0) 48(58.42,2.54) 49(60.96,0) 50(60.96,2.54) 51(63.5,0) 52(63.5,2.54) 53(66.04,0) 54(66.04,2.54) 55(68.58,0) 56(68.58,2.54) 57(71.12,0) 58(71.12,2.54) 59(73.66,0) 60(73.66,2.54) 61(76.2,0) 62(76.2,2.54) 63(78.74,0) 64(78.74,2.54) 65(81.28,0) 66(81.28,2.54) 67(83.82,0) 68(83.82,2.54) 69(86.36,0) 70(86.36,2.54) 71(88.9,0) 72(88.9,2.54)
  silkscreen extent -1.27,-2.03 90.17,3.81, body extent -1.27,-1.27 90.17,3.81, height 9
HDR_4x2_2R54_V_M [mm]
  rect 1.5x1.5 hole 1.02: 1(0,0)
  round 1.5 hole 1.02: 2(0,2.54) 3(2.54,0) 4(2.54,2.54) 5(5.08,0) 6(5.08,2.54) 7(7.62,0) 8(7.62,2.54)
  silkscreen extent -1.27,-1.89 8.89,3.81, body extent -1.27,-1.27 8.89,3.81, height 9
HDR_8x2_2R54_V_F [mm] "Female Header, Pitch 2.54mm, 2x8 Position, Mated Height 6mm, Tail Length 3mm"
  rect 1.5x1.8 hole 1.02: 1(0,0)
  oval 1.5x1.8 hole 1.02: 2(0,2.54) 3(2.54,0) 4(2.54,2.54) 5(5.08,0) 6(5.08,2.54) 7(7.62,0) 8(7.62,2.54) 9(10.16,0) 10(10.16,2.54) 11(12.7,0) 12(12.7,2.54) 13(15.24,0) 14(15.24,2.54) 15(17.78,0) 16(17.78,2.54)
  silkscreen extent -1.96,-1.27 19.05,3.81, body extent -1.27,-1.27 19.05,3.81, height 8.64
HDR_10x2_2R54_V_F [mm] "Female Header, Pitch 2.54mm, 2x8 Position, Mated Height 6mm, Tail Length 3mm"
  rect 1.5x1.8 hole 1.02: 1(0,0)
  oval 1.5x1.8 hole 1.02: 2(0,2.54) 3(2.54,0) 4(2.54,2.54) 5(5.08,0) 6(5.08,2.54) 7(7.62,0) 8(7.62,2.54) 9(10.16,0) 10(10.16,2.54) 11(12.7,0) 12(12.7,2.54) 13(15.24,0) 14(15.24,2.54) 15(17.78,0) 16(17.78,2.54) 17(20.32,0) 18(20.32,2.54) 19(22.86,0) 20(22.86,2.54)
  silkscreen extent -1.27,-2.09 24.13,3.81, body extent -1.27,-1.27 24.13,3.81, height 8.64
HDR_15x2_2R54_V_F [mm] "Female Header, Pitch 2.54mm, 2x15 Position, Mated Height 6mm, Tail Length 3mm"
  rect 1.5x1.8 hole 1.02: 1(0,0)
  oval 1.5x1.8 hole 1.02: 2(0,2.54) 3(2.54,0) 4(2.54,2.54) 5(5.08,0) 6(5.08,2.54) 7(7.62,0) 8(7.62,2.54) 9(10.16,0) 10(10.16,2.54) 11(12.7,0) 12(12.7,2.54) 13(15.24,0) 14(15.24,2.54) 15(17.78,0) 16(17.78,2.54) 17(20.32,0) 18(20.32,2.54) 19(22.86,0) 20(22.86,2.54) 21(25.4,0) 22(25.4,2.54) 23(27.94,0) 24(27.94,2.54) 25(30.48,0) 26(30.48,2.54) 27(33.02,0) 28(33.02,2.54) 29(35.56,0) 30(35.56,2.54)
  silkscreen extent -2.01,-1.27 36.83,3.81, body extent -1.27,-1.27 36.83,3.81, height 8.64
HDR_17x2_2R54_V_F [mm] "Female Header, Pitch 2.54mm, 2x17 Position, Mated Height 6mm, Tail Length 3mm"
  rect 1.5x1.8 hole 1.02: 1(0,0)
  oval 1.5x1.8 hole 1.02: 2(0,2.54) 3(2.54,0) 4(2.54,2.54) 5(5.08,0) 6(5.08,2.54) 7(7.62,0) 8(7.62,2.54) 9(10.16,0) 10(10.16,2.54) 11(12.7,0) 12(12.7,2.54) 13(15.24,0) 14(15.24,2.54) 15(17.78,0) 16(17.78,2.54) 17(20.32,0) 18(20.32,2.54) 19(22.86,0) 20(22.86,2.54) 21(25.4,0) 22(25.4,2.54) 23(27.94,0) 24(27.94,2.54) 25(30.48,0) 26(30.48,2.54) 27(33.02,0) 28(33.02,2.54) 29(35.56,0) 30(35.56,2.54) 31(38.1,0) 32(38.1,2.54) 33(40.64,0) 34(40.64,2.54)
  silkscreen extent -1.98,-1.27 41.91,3.81, body extent -1.27,-1.27 41.91,3.81, height 8.64
HSMF-A201 [mm] "LED"
  rect 1.5x1.1 smd: 1(-1.5,0.75) 2(1.5,0.75) 3(1.5,-0.75) 4(-1.5,-0.75)
  silkscreen extent -2.89,-1.55 1.75,1.55, body extent -1.6,-1.4 1.6,1.4, height 1.2
L1008_L0805_CPT [mm]
  rect 0.6x2 smd: 1(-0.95,0) 2(0.95,0)
  body extent -1.24,-0.89 1.24,0.89, height 0.75
LQFP48_0R5_7x7 [mm] "Low & medium-density value line, advanced ARM-based 32-bit MCU"
  rect 0.2x1 smd: 1(-2.75,-4.25) 2(-2.25,-4.25) 3(-1.75,-4.25) 4(-1.25,-4.25) 5(-0.75,-4.25) 6(-0.25,-4.25) 7(0.25,-4.25) 8(0.75,-4.25) 9(1.25,-4.25) 10(1.75,-4.25) 11(2.25,-4.25) 12(2.75,-4.25) 25(2.75,4.25) 26(2.25,4.25) 27(1.75,4.25) 28(1.25,4.25) 29(0.75,4.25) 30(0.25,4.25) 31(-0.25,4.25) 32(-0.75,4.25) 33(-1.25,4.25) 34(-1.75,4.25) 35(-2.25,4.25) 36(-2.75,4.25)
  rect 1x0.2 smd: 13(4.25,-2.75) 14(4.25,-2.25) 15(4.25,-1.75) 16(4.25,-1.25) 17(4.25,-0.75) 18(4.25,-0.25) 19(4.25,0.25) 20(4.25,0.75) 21(4.25,1.25) 22(4.25,1.75) 23(4.25,2.25) 24(4.25,2.75) 37(-4.25,2.75) 38(-4.25,2.25) 39(-4.25,1.75) 40(-4.25,1.25) 41(-4.25,0.75) 42(-4.25,0.25) 43(-4.25,-0.25) 44(-4.25,-0.75) 45(-4.25,-1.25) 46(-4.25,-1.75) 47(-4.25,-2.25) 48(-4.25,-2.75)
  silkscreen extent -3.81,-5.52 3.81,3.81, body extent -3.5,-3.5 3.5,3.5, height 1.6
LQFP144_0R5_SKT [mm] "32-bit MCU ARM-based Cortex-M3 20 X 20mm, 0.5mm Pitch, 1.6mm Max thickness"
  rect 1x2.5 smd rot 45: 0(-10.96,-10.96) 0(10.96,10.96)
  rect 1x2.5 smd rot 135: 0(-10.96,10.96) 0(10.96,-10.96)
  round 1.5 hole 1.5 unplated: 0(0,-8) 0(0,8)
  rect 0.3x1.65 smd: 1(-8.75,-10.625) 2(-8.25,-10.625) 3(-7.75,-10.625) 4(-7.25,-10.625) 5(-6.75,-10.625) 6(-6.25,-10.625) 7(-5.75,-10.625) 8(-5.25,-10.625) 9(-4.75,-10.625) 10(-4.25,-10.625) 11(-3.75,-10.625) 12(-3.25,-10.625) 13(-2.75,-10.625) 14(-2.25,-10.625) 15(-1.75,-10.625) 16(-1.25,-10.625) 17(-0.75,-10.625) 18(-0.25,-10.625) 19(0.25,-10.625) 20(0.75,-10.625) 21(1.25,-10.625) 22(1.75,-10.625) 23(2.25,-10.625) 24(2.75,-10.625) 25(3.25,-10.625) 26(3.75,-10.625) 27(4.25,-10.625) 28(4.75,-10.625) 29(5.25,-10.625) 30(5.75,-10.625) 31(6.25,-10.625) 32(6.75,-10.625) 33(7.25,-10.625) 34(7.75,-10.625) 35(8.25,-10.625) 36(8.75,-10.625) 73(8.75,10.625) 74(8.25,10.625) 75(7.75,10.625) 76(7.25,10.625) 77(6.75,10.625) 78(6.25,10.625) 79(5.75,10.625) 80(5.25,10.625) 81(4.75,10.625) 82(4.25,10.625) 83(3.75,10.625) 84(3.25,10.625) 85(2.75,10.625) 86(2.25,10.625) 87(1.75,10.625) 88(1.25,10.625) 89(0.75,10.625) 90(0.25,10.625) 91(-0.25,10.625) 92(-0.75,10.625) 93(-1.25,10.625) 94(-1.75,10.625) 95(-2.25,10.625) 96(-2.75,10.625) 97(-3.25,10.625) 98(-3.75,10.625) 99(-4.25,10.625) 100(-4.75,10.625) 101(-5.25,10.625) 102(-5.75,10.625) 103(-6.25,10.625) 104(-6.75,10.625) 105(-7.25,10.625) 106(-7.75,10.625) 107(-8.25,10.625) 108(-8.75,10.625)
  rect 1.65x0.3 smd: 37(10.625,-8.75) 38(10.625,-8.25) 39(10.625,-7.75) 40(10.625,-7.25) 41(10.625,-6.75) 42(10.625,-6.25) 43(10.625,-5.75) 44(10.625,-5.25) 45(10.625,-4.75) 46(10.625,-4.25) 47(10.625,-3.75) 48(10.625,-3.25) 49(10.625,-2.75) 50(10.625,-2.25) 51(10.625,-1.75) 52(10.625,-1.25) 53(10.625,-0.75) 54(10.625,-0.25) 55(10.625,0.25) 56(10.625,0.75) 57(10.625,1.25) 58(10.625,1.75) 59(10.625,2.25) 60(10.625,2.75) 61(10.625,3.25) 62(10.625,3.75) 63(10.625,4.25) 64(10.625,4.75) 65(10.625,5.25) 66(10.625,5.75) 67(10.625,6.25) 68(10.625,6.75) 69(10.625,7.25) 70(10.625,7.75) 71(10.625,8.25) 72(10.625,8.75) 109(-10.625,8.75) 110(-10.625,8.25) 111(-10.625,7.75) 112(-10.625,7.25) 113(-10.625,6.75) 114(-10.625,6.25) 115(-10.625,5.75) 116(-10.625,5.25) 117(-10.625,4.75) 118(-10.625,4.25) 119(-10.625,3.75) 120(-10.625,3.25) 121(-10.625,2.75) 122(-10.625,2.25) 123(-10.625,1.75) 124(-10.625,1.25) 125(-10.625,0.75) 126(-10.625,0.25) 127(-10.625,-0.25) 128(-10.625,-0.75) 129(-10.625,-1.25) 130(-10.625,-1.75) 131(-10.625,-2.25) 132(-10.625,-2.75) 133(-10.625,-3.25) 134(-10.625,-3.75) 135(-10.625,-4.25) 136(-10.625,-4.75) 137(-10.625,-5.25) 138(-10.625,-5.75) 139(-10.625,-6.25) 140(-10.625,-6.75) 141(-10.625,-7.25) 142(-10.625,-7.75) 143(-10.625,-8.25) 144(-10.625,-8.75)
  silkscreen extent -10,-12.27 10,10, body extent -17.12,-17.12 17.12,17.13, height 14.3
"Micro-AB or MicroB" [mm]
  rect 0.4x1.35 smd: 1(-1.3,1.25) 2(-0.65,1.25) 3(0,1.25) 4(0.65,1.25) 5(1.3,1.25)
  oval 1.6x2 hole 1.2 slot 1.5 at 90 deg: 6(-2.519,1.45) 11(2.51,1.45)
  rect 2.4x1.9 hole 1.5 square copper offset 0.25,0: 7(-3.75,-1.45)
  rect 1.8x1.9 smd: 8(-1.15,-1.45) 9(1.15,-1.45)
  rect 2.4x1.9 hole 1.5 square copper offset -0.25,0: 10(3.75,-1.45)
  silkscreen extent -3.95,-0.21 3.95,2.62, body extent -4.1,-3.96 4.1,1.44, height 2.58
Molex_1050170001 [mm] "USB Micro-B Connector"
  rect 0.4x1.35 smd: 1(-1.3,0) 2(-0.65,0) 3(0,0) 4(0.65,0) 5(1.3,0)
  round 1.45 hole 0.85: 6(-2.5,0) 11(2.5,0)
  rect 1.8x1.9 hole 0.6 slot 1.3 at 90 deg copper offset 0.3,0: 7(-3.5,-2.7)
  rect 1.5x1.9 smd: 8(-1,-2.7) 9(1,-2.7)
  rect 1.8x1.9 hole 0.6 slot 1.3 at 90 deg copper offset -0.3,0: 10(3.5,-2.7)
  silkscreen extent -3.95,-1.46 3.95,1.37, body extent -4.1,-5.21 4.1,0.19, height 2.58
OSC_2SM_3R2x2R5 [mm] "Crystal 8M Hz 3.2x2.5mm SMD"
  rect 1.5x2.7 smd: 1(-0.95,0) 2(0.95,0)
  body extent -1.6,-1.25 1.6,1.25, height 1
PB-6X6mm-Black [mm] "Surface Mounting Type Tact Switch, 4-Leads, Body 6x6mm, Height 4.5mm Black"
  rect 2.3x1.8 smd: 1(4.325,2.25) 2(4.325,-2.25) 3(-4.325,-2.25) 4(-4.325,2.25)
  silkscreen extent -2.83,-3 2.81,3, body extent -3,-3 3,3, height 10.5
PB-6X6mm-Blue [mm] "Surface Mounting Type Tact Switch, 4-Leads, Body 6x6mm, Height 4.5mm,Blue"
  rect 2.3x1.8 smd: 1(4.325,2.25) 2(4.325,-2.25) 3(-4.325,-2.25) 4(-4.325,2.25)
  silkscreen extent -2.83,-3 2.81,3, body extent -3,-3 3,3, height 10.5
QFN0P170X200X55-12N [mm]
  rect 0.5x0.25 smd: 1(-0.625,0.8) 2(-0.625,0.4) 3(-0.625,0) 4(-0.625,-0.4) 5(-0.625,-0.8) 7(0.625,-0.8) 8(0.625,-0.4) 9(0.625,0) 10(0.625,0.4) 11(0.625,0.8)
  rect 0.25x0.5 smd: 6(0,-0.75) 12(0,0.75)
  silkscreen extent -1.35,0.76 -1.25,0.86, body extent -0.85,-1 0.85,1, height 0.55
QFN40P180X140X55-10N [mm]
  rect 0.5x0.25 smd: 1(-0.75,0.4) 2(-0.75,0) 3(-0.75,-0.4) 6(0.75,-0.4) 7(0.75,0) 8(0.75,0.4)
  rect 0.25x0.5 smd: 4(-0.2,-0.5) 5(0.2,-0.5) 9(0.2,0.5) 10(-0.2,0.5)
  silkscreen extent -1.55,0.33 -1.45,0.43, body extent -0.9,-0.65 0.9,0.65, height 0.5
SB_0603 [mil] "Jumper"
  rect 32x40 smd: 1(33.75,0) 2(-33.75,0)
  Top Layer region: 23.75,20 13.75,20 -6.25,0 13.75,-20 23.75,-20
  Top Layer region: -26.25,0 -16.25,0 3.75,20 -26.25,20
  Top Layer region: -26.25,0 -16.25,0 3.75,-20 -26.25,-20
SOD-323 [mm] "Diode"
  rect 1.35x0.4 smd: 1(-1.2,0) 2(1.2,0)
  silkscreen extent -1.4,-0.75 1.4,1.24, body extent -1.35,-0.72 1.35,0.72, height 1.17
SOIC8_1R27_4R9X6 [mm] "1.2 A current limited high-side power switch with thermal shutdown"
  rect 2.2x0.6 smd: 1(-2.425,1.905) 2(-2.425,0.635) 3(-2.425,-0.635) 4(-2.425,-1.905) 5(2.425,-1.905) 6(2.425,-0.635) 7(2.425,0.635) 8(2.425,1.905)
  silkscreen extent -2.67,-2.5 0.93,3.08, body extent -2,-2.5 2,2.5, height 1.45
SOT23-5 [mm]
  rect 1.2x0.6 smd: 1(-1.15,0.95) 2(-1.15,0) 3(-1.15,-0.95) 4(1.15,-0.95) 5(1.15,0.95)
  silkscreen extent -0.84,-1.46 0.81,1.46, body extent -0.87,-1.5 0.88,1.5, height 1.45
SOT23-6L [mm]
  rect 1.1x0.6 smd: 1(-1.2,0.95) 2(-1.2,0) 3(-1.2,-0.95) 4(1.2,-0.95) 5(1.2,0) 6(1.2,0.95)
  silkscreen extent -1.32,-1.5 0.25,1.93, body extent -0.86,-1.51 0.87,1.52, height 1.25
SOT-23 [mm]
  rect 0.8x0.9 smd: 1(-0.98,-1) 2(0.98,-1) 3(0,1)
  silkscreen extent -2,-1.52 1.5,0.7, body extent -1.52,-0.7 1.52,0.7, height 1.11
SOT-23-5L [mil] "Enhanced single channel power switches"
  rect 30x16 smd: 1(-53.15,37.4) 2(-53.15,0) 3(-53.15,-37.4) 4(53.15,-37.4) 5(53.15,37.4)
  silkscreen extent -33,-58 32,57, body extent -34,-59 34,59, height 57
SOT-223 [mil] "Adjustable and fixed low drop positive voltage regulator"
  rect 80x40 smd: 1(-125,93) 2(-125,0) 3(-125,-93)
  rect 90x120 smd: 4(125,0)
  silkscreen extent -62,-149 48,141, body extent -84,-132 62,132, height 71
TAN-A [mil] "TAN Capacitor"
  rect 50x60 smd: 1(55,0) 2(-55,0)
  silkscreen extent -95,-45 95,80, body extent -47,-35 47,35, height 39
TAN-B [mm] "Tan Capacitor"
  rect 1.5x2.8 smd: 1(1.55,0) 2(-1.55,0)
  silkscreen extent -2.79,-1.9 3.56,1.91, body extent -1.76,-1.54 1.7,1.54, height 1
TP [mm] "Testpoint, Surface Mounting, Circular, Pad Diameter 1mm"
  round 1 smd: 1(0,0)
USOP8_0R5_2X3R1 [mm]
  rect 0.8x0.3 smd: 1(-1.55,0.75) 2(-1.55,0.25) 3(-1.55,-0.25) 4(-1.55,-0.75) 5(1.55,-0.75) 6(1.55,-0.25) 7(1.55,0.25) 8(1.55,0.75)
  silkscreen extent -2.76,-1.05 0.3,1.05, body extent -1.2,-1.05 1.2,1.05, height 0.9
WLCSP-9ball [mm]
  round 0.32 smd: A1(-0.5,0.5) A2(0,0.5) A3(0.5,0.5) B1(-0.5,0) B2(0,0) B3(0.5,0) C1(-0.5,-0.5) C2(0,-0.5) C3(0.5,-0.5)
  body extent -0.82,-0.92 0.83,0.93, height 0.6
XTAL_2SM_3R2X1R5 [mm] "CRYSTAL 32.768KHZ 6PF SMD 2 pads"
  rect 1x1.8 smd: 1(-1.25,0) 2(1.25,0)
  silkscreen extent -0.28,-0.91 0.28,0.91, body extent -1.63,-0.75 1.58,0.75, height 0.89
